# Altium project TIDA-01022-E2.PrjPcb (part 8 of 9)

## Sheet TIDA-01022-E2_Power3.SchDoc: Power Supplies
size 431 x 279 mm; Date: Not shown in title block; ApprovedBy: Not shown in title block; CheckedBy: Not shown in title block; Author: Not shown in title block; CompanyName: Not shown in title block; DrawnBy: Avinash N; Engineer: Not shown in title block; Organization: Not shown in title block; Address1: Not shown in title block; Address2: Not shown in title block; Address3: Not shown in title block; Address4: Not shown in title block; DocumentNumber: 1; Revision: Use project parameter SCH_Rev; SheetNumber: 23; SheetTotal: 26; PageSetup: Record=PageOptions¦CenterHorizontal=True¦CenterVertical=True¦PrintScale=1.00¦XCorrection=1.00¦YCorrection=1.00¦PrintKind=0¦BorderSize=5000000¦LeftOffset=0¦BottomOffset=0¦Orientation=2¦PaperLength=1000¦PaperWidth=1000¦Scale=100¦PaperSource=15¦PrintQuality=600¦MediaType=1¦DitherType=10¦PaperKind=Letter¦PrintScaleMode=1
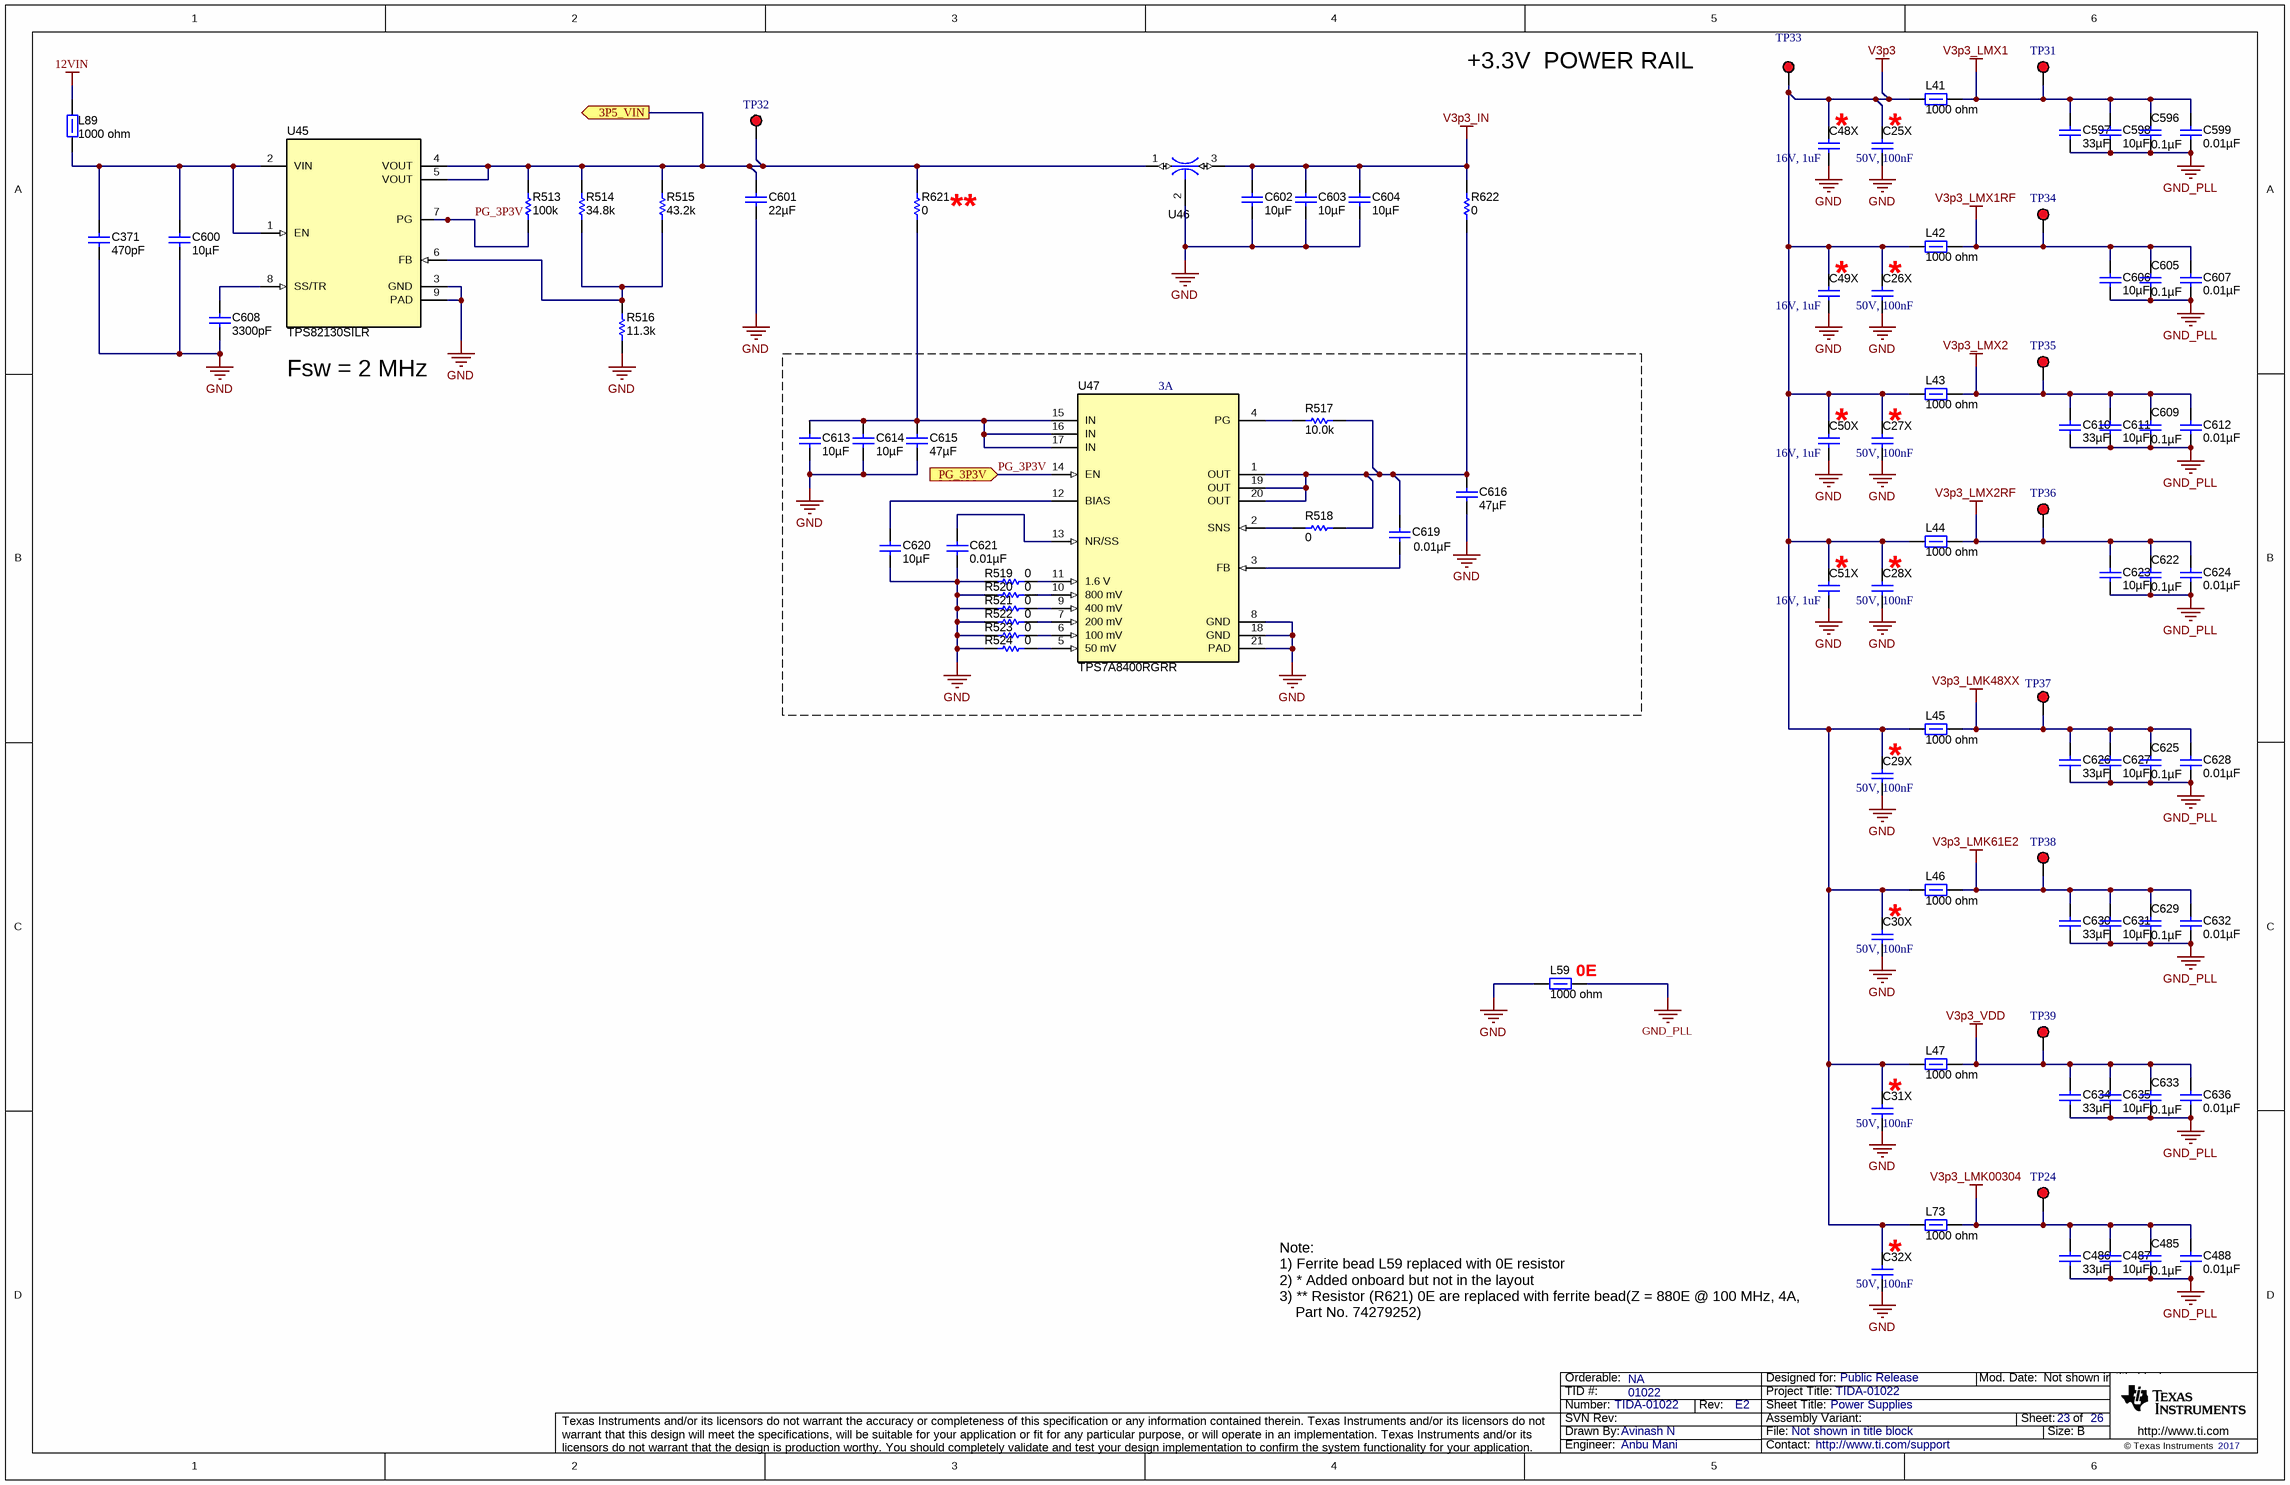
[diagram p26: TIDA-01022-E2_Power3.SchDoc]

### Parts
C25X  50V, 100nF  [0603_1.6x0.8x0.8mm_Reflow Soldering]
C26X  50V, 100nF  [0603_1.6x0.8x0.8mm_Reflow Soldering]
C27X  50V, 100nF  [0603_1.6x0.8x0.8mm_Reflow Soldering]
C28X  50V, 100nF  [0603_1.6x0.8x0.8mm_Reflow Soldering]
C29X  50V, 100nF  [0603_1.6x0.8x0.8mm_Reflow Soldering]
C30X  50V, 100nF  [0603_1.6x0.8x0.8mm_Reflow Soldering]
C31X  50V, 100nF  [0603_1.6x0.8x0.8mm_Reflow Soldering]
C32X  50V, 100nF  [0603_1.6x0.8x0.8mm_Reflow Soldering]
C48X  16V, 1uF  [0603_1.6x0.8x0.8mm_Reflow Soldering]
C49X  16V, 1uF  [0603_1.6x0.8x0.8mm_Reflow Soldering]
C50X  16V, 1uF  [0603_1.6x0.8x0.8mm_Reflow Soldering]
C51X  16V, 1uF  [0603_1.6x0.8x0.8mm_Reflow Soldering]
C371  ValueDisplayed: 470pF  [0402]  (hidden comment: GRM1555C1H471JA01D)
C485  ValueDisplayed: 0.1µF  [0603]  (hidden comment: CGA3E2X7R1H104K080AA)
C486  ValueDisplayed: 33µF  [1206_180]  (hidden comment: C3216X5R1E336M160AC)
C487  ValueDisplayed: 10µF  [1206_190]  (hidden comment: C3216X7R1E106M160AE)
C488  ValueDisplayed: 0.01µF  [0603]  (hidden comment: GCM188R71H103KA37D)
C596  ValueDisplayed: 0.1µF  [0603]  (hidden comment: CGA3E2X7R1H104K080AA)
C597  ValueDisplayed: 33µF  [1206_180]  (hidden comment: C3216X5R1E336M160AC)
C598  ValueDisplayed: 10µF  [1206_190]  (hidden comment: C3216X7R1E106M160AE)
C599  ValueDisplayed: 0.01µF  [0603]  (hidden comment: GCM188R71H103KA37D)
C600  ValueDisplayed: 10µF  [1206_190]  (hidden comment: C3216X7R1E106M160AE)
C601  ValueDisplayed: 22µF  [0805_HV]  (hidden comment: JMK212BJ226MG-T)
C602  ValueDisplayed: 10µF  [1206_190]  (hidden comment: C3216X7R1E106M160AE)
C603  ValueDisplayed: 10µF  [1206_190]  (hidden comment: C3216X7R1E106M160AE)
C604  ValueDisplayed: 10µF  [1206_190]  (hidden comment: C3216X7R1E106M160AE)
C605  ValueDisplayed: 0.1µF  [0603]  (hidden comment: CGA3E2X7R1H104K080AA)
C606  ValueDisplayed: 10µF  [1206_190]  (hidden comment: C3216X7R1E106M160AE)
C607  ValueDisplayed: 0.01µF  [0603]  (hidden comment: GCM188R71H103KA37D)
C608  ValueDisplayed: 3300pF  [0603]  (hidden comment: GRM1885C1H332JA01D)
C609  ValueDisplayed: 0.1µF  [0603]  (hidden comment: CGA3E2X7R1H104K080AA)
C610  ValueDisplayed: 33µF  [1206_180]  (hidden comment: C3216X5R1E336M160AC)
C611  ValueDisplayed: 10µF  [1206_190]  (hidden comment: C3216X7R1E106M160AE)
C612  ValueDisplayed: 0.01µF  [0603]  (hidden comment: GCM188R71H103KA37D)
C613  ValueDisplayed: 10µF  [0805_HV]  (hidden comment: GRM21BR61C106KE15L)
C614  ValueDisplayed: 10µF  [0805_HV]  (hidden comment: GRM21BR61C106KE15L)
C615  ValueDisplayed: 47µF  [0805_HV]  (hidden comment: GRM219R60G476ME44D)
C616  ValueDisplayed: 47µF  [0805_HV]  (hidden comment: GRM219R60G476ME44D)
C619  ValueDisplayed: 0.01µF  [0603]  (hidden comment: GRM188R71H103KA01D)
C620  ValueDisplayed: 10µF  [0805_HV]  (hidden comment: GRM21BR61C106KE15L)
C621  ValueDisplayed: 0.01µF  [0603]  (hidden comment: GRM188R71H103KA01D)
C622  ValueDisplayed: 0.1µF  [0603]  (hidden comment: CGA3E2X7R1H104K080AA)
C623  ValueDisplayed: 10µF  [1206_190]  (hidden comment: C3216X7R1E106M160AE)
C624  ValueDisplayed: 0.01µF  [0603]  (hidden comment: GCM188R71H103KA37D)
C625  ValueDisplayed: 0.1µF  [0603]  (hidden comment: CGA3E2X7R1H104K080AA)
C626  ValueDisplayed: 33µF  [1206_180]  (hidden comment: C3216X5R1E336M160AC)
C627  ValueDisplayed: 10µF  [1206_190]  (hidden comment: C3216X7R1E106M160AE)
C628  ValueDisplayed: 0.01µF  [0603]  (hidden comment: GCM188R71H103KA37D)
C629  ValueDisplayed: 0.1µF  [0603]  (hidden comment: CGA3E2X7R1H104K080AA)
C630  ValueDisplayed: 33µF  [1206_180]  (hidden comment: C3216X5R1E336M160AC)
C631  ValueDisplayed: 10µF  [1206_190]  (hidden comment: C3216X7R1E106M160AE)
C632  ValueDisplayed: 0.01µF  [0603]  (hidden comment: GCM188R71H103KA37D)
C633  ValueDisplayed: 0.1µF  [0603]  (hidden comment: CGA3E2X7R1H104K080AA)
C634  ValueDisplayed: 33µF  [1206_180]  (hidden comment: C3216X5R1E336M160AC)
C635  ValueDisplayed: 10µF  [1206_190]  (hidden comment: C3216X7R1E106M160AE)
C636  ValueDisplayed: 0.01µF  [0603]  (hidden comment: GCM188R71H103KA37D)
L41  ValueDisplayed: 1000 ohm  [1806_HighSpeed]  (hidden comment: BLM41PG102SN1L)
L42  ValueDisplayed: 1000 ohm  [1806_HighSpeed]  (hidden comment: BLM41PG102SN1L)
L43  ValueDisplayed: 1000 ohm  [1806_HighSpeed]  (hidden comment: BLM41PG102SN1L)
L44  ValueDisplayed: 1000 ohm  [1806_HighSpeed]  (hidden comment: BLM41PG102SN1L)
L45  ValueDisplayed: 1000 ohm  [1806_HighSpeed]  (hidden comment: BLM41PG102SN1L)
L46  ValueDisplayed: 1000 ohm  [1806_HighSpeed]  (hidden comment: BLM41PG102SN1L)
L47  ValueDisplayed: 1000 ohm  [1806_HighSpeed]  (hidden comment: BLM41PG102SN1L)
L59  ValueDisplayed: 1000 ohm  [1806_HighSpeed]  (hidden comment: BLM41PG102SN1L)
L73  ValueDisplayed: 1000 ohm  [1806_HighSpeed]  (hidden comment: BLM41PG102SN1L)
L89  ValueDisplayed: 1000 ohm  [1806_HighSpeed]  (hidden comment: BLM41PG102SN1L)
R513  ValueDisplayed: 100k  [0402]  (hidden comment: CRCW0402100KFKED)
R514  ValueDisplayed: 34.8k  [0603]  (hidden comment: CRCW060334K8FKEA)
R515  ValueDisplayed: 43.2k  [0402]  (hidden comment: CRCW040243K2FKED)
R516  ValueDisplayed: 11.3k  [0402]  (hidden comment: CRCW040211K3FKED)
R517  ValueDisplayed: 10.0k  [0603]  (hidden comment: CRCW060310K0FKEA)
R518  ValueDisplayed: 0  [0603]  (hidden comment: CRCW06030000Z0EA)
R519  ValueDisplayed: 0  [0402]  (hidden comment: CRCW04020000Z0ED)
R520  ValueDisplayed: 0  [0402]  (hidden comment: CRCW04020000Z0ED)
R521  ValueDisplayed: 0  [0402]  (hidden comment: CRCW04020000Z0ED)
R522  ValueDisplayed: 0  [0402]  (hidden comment: CRCW04020000Z0ED)
R523  ValueDisplayed: 0  [0402]  (hidden comment: CRCW04020000Z0ED)
R524  ValueDisplayed: 0  [0402]  (hidden comment: CRCW04020000Z0ED)
R621  ValueDisplayed: 0  [1206]  (hidden comment: CRCW12060000Z0EA)
R622  ValueDisplayed: 0  [1206]  (hidden comment: CRCW12060000Z0EA)
TP24  5000  [Keystone5000]  (value not drawn)
TP31  5000  [Keystone5000]  (value not drawn)
TP32  5000  [Keystone5000]  (value not drawn)
TP33  5000  [Keystone5000]  (value not drawn)
TP34  5000  [Keystone5000]  (value not drawn)
TP35  5000  [Keystone5000]  (value not drawn)
TP36  5000  [Keystone5000]  (value not drawn)
TP37  5000  [Keystone5000]  (value not drawn)
TP38  5000  [Keystone5000]  (value not drawn)
TP39  5000  [Keystone5000]  (value not drawn)
U45  TPS82130SILR  [SIL0008D_SMD]
U46  NFM31PC276B0J3L  [Murata_NFM31P]  (value not drawn)
U47  TPS7A8400RGRR  [RGR0020A]

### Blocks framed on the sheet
3A: C613-C616 C619-C621 R517-R524 U47

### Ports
3P5_VIN (out), PG_3P3V (in)

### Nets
12VIN: L89.2
GND: C25X.1 C26X.1 C27X.1 C28X.1 C29X.1 C30X.1 C31X.1 C32X.1 C48X.2 C49X.2 C50X.2 C51X.2 C371.2 C600.2 C601.2 C602.1 C603.1 C604.1 C608.1 C613.2 C614.2 C615.2 C616.2 C620.2 C621.2 L59.1 R516.1 R519.1 R520.1 R521.1 R522.1 R523.1 R524.1 U45.3(GND) U45.9(PAD) U46.2 U47.8(GND) U47.18(GND) U47.21(PAD)
GND_PLL: C485.2 C486.2 C487.1 C488.2 C596.2 C597.2 C598.1 C599.2 C605.2 C606.1 C607.2 C609.2 C610.2 C611.1 C612.2 C622.2 C623.1 C624.2 C625.2 C626.2 C627.1 C628.2 C629.2 C630.2 C631.1 C632.2 C633.2 C634.2 C635.1 C636.2 L59.2  [project net DGND]
V3p3: C25X.2 C26X.2 C27X.2 C28X.2 C29X.2 C30X.2 C31X.2 C32X.2 C48X.1 C49X.1 C50X.1 C51X.1 L41.1 L42.1 L43.1 L44.1 L45.1 L46.1 L47.1 L73.1 TP33.1
V3p3_IN: C602.2 C603.2 C604.2 R622.2 U46.3
V3p3_LMK48XX: C625.1 C626.1 C627.2 C628.1 L45.2 TP37.1
V3p3_LMK61E2: C629.1 C630.1 C631.2 C632.1 L46.2 TP38.1
V3p3_LMK00304: C485.1 C486.1 C487.2 C488.1 L73.2 TP24.1
V3p3_LMX1: C596.1 C597.1 C598.2 C599.1 L41.2 TP31.1
V3p3_LMX1RF: C605.1 C606.2 C607.1 L42.2 TP34.1
V3p3_LMX2: C609.1 C610.1 C611.2 C612.1 L43.2 TP35.1
V3p3_LMX2RF: C622.1 C623.2 C624.1 L44.2 TP36.1
V3p3_VDD: C633.1 C634.1 C635.2 C636.1 L47.2 TP39.1
3P5_VIN: C601.1 R513.2 R514.2 R515.2 R621.2 TP32.1 U45.4(VOUT) U45.5(VOUT) U46.1 ; port 3P5_VIN
PG_3P3V: R513.1 U45.7(PG) U47.14(EN) ; port PG_3P3V
NetC371_1: C371.1 C600.1 L89.1 U45.1(EN) U45.2(VIN)
NetC608_2: C608.2 U45.8(SS/TR)
NetC613_1: C613.1 C614.1 C615.1 R621.1 U47.15(IN) U47.16(IN) U47.17(IN)
NetC616_1: C616.1 C619.1 R517.1 R518.2 R622.1 U47.1(OUT) U47.19(OUT) U47.20(OUT)
NetC619_2: C619.2 U47.3(FB)
NetC620_1: C620.1 U47.12(BIAS)
NetC621_1: C621.1 U47.13(NR/SS)
NetR514_1: R514.1 R515.1 R516.2 U45.6(FB)
NetR517_2: R517.2 U47.4(PG)
NetR518_1: R518.1 U47.2(SNS)
NetR519_2: R519.2 U47.11(1.6_V)
NetR520_2: R520.2 U47.10(800_mV)
NetR521_2: R521.2 U47.9(400_mV)
NetR522_2: R522.2 U47.7(200_mV)
NetR523_2: R523.2 U47.6(100_mV)
NetR524_2: R524.2 U47.5(50_mV)

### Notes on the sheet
- +3.3V  POWER RAIL
- (near C48X) *
- (near C25X) *
- (near R621) *
- (near C49X) *
- (near C26X) *
- Fsw = 2 MHz
- (near C50X) *
- (near C27X) *
- (near C51X) *
- (near C28X) *
- (near C29X) *
- (near L59) 0E
- (near C30X) *
- (near C31X) *
- (near C32X) *
- Note:
  1) Ferrite bead L59 replaced with 0E resistor
  2) * Added onboard but not in the layout
  3) ** Resistor (R621) 0E are replaced with ferrite bead(Z = 880E @ 100 MHz, 4A,
  Part No. 74279252)

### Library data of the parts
C25X C26X C27X C28X C29X C30X C31X C32X = 885012206095: WCAP-CSGP Ceramic Capacitors, 0603, X7R, 50V, 100nF; Rated Voltage: 50V DC
C48X C49X C50X C51X = 885012206052: WCAP-CSGP Ceramic Capacitors, 0603, X7R, 16V, 1uF; Rated Voltage: 16V DC
C371 = GRM1555C1H471JA01D: CAP, CERM, 470 pF, 50 V, +/- 5%, C0G/NP0, 0402; Manufacturer: MuRata; Polarized: N; CompType: Capacitor; Value: 470pF; U/M: EA; Cap_F: 0.00000000047; Tolerance_%: 5; Value1: Unknown; VDC_V: 50; Value2: 50V; TaMin_C: -55; TaMax_C: 125; SizeArea_mm2: 0.5; SizeAreaWB_mm2: 3; SizeX_mm: 1; SizeZ_mm: 0.6; AEC Category: Q200
C485 C596 C605 C609 C622 C625 C629 C633 = CGA3E2X7R1H104K080AA: CAP, CERM, 0.1 µF, 50 V, +/- 10%, X7R, AEC-Q200 Grade 1, 0603; Manufacturer: TDK; Polarized: N; CompType: Capacitor; Value: 0.1uF; U/M: EA; Cap_F: 0.0000001; Tolerance_%: 10; ESR_ohm: 0.0296; Value1: 0.0296 ohm; VDC_V: 50; Value2: 50V; IRMS_A: 0.97199; TaMin_C: -55; TaMax_C: 125; SizeArea_mm2: 1.28; SizeAreaWB_mm2: 4.68; SizeX_mm: 1.6; SizeY_mm: 0.8; SizeZ_mm: 1; AEC Category: Q200; AEC Qualified: Y
C486 C597 C610 C626 C630 C634 = C3216X5R1E336M160AC: CAP, CERM, 33 µF, 25 V, +/- 20%, X5R, 1206; Manufacturer: TDK; Polarized: N; CompType: Capacitor; Value: 33uF; U/M: EA; Cap_F: 0.000033; Tolerance_%: 20; ESR_ohm: 0.002648; Value1: 0.002648 ohm; VDC_V: 25; Value2: 25V; IRMS_A: 4.45864; TaMin_C: -55; TaMax_C: 85; SizeArea_mm2: 5.12; SizeAreaWB_mm2: 10.92; SizeX_mm: 3.2; SizeY_mm: 1.6; SizeZ_mm: 1.8; AEC Category: Q200
C487 C598 C600 C602-C604 C606 C611 C623 C627 C631 C635 = C3216X7R1E106M160AE: CAP, CERM, 10 µF, 25 V, +/- 20%, X7R, 1206_190; Manufacturer: TDK; Polarized: N; CompType: Capacitor; Value: 10uF; U/M: EA; Cap_F: 0.00001; Tolerance_%: 20; Value1: Unknown; VDC_V: 25; Value2: 25V; TaMin_C: -55; TaMax_C: 125; Cap_Case: 1206; SizeArea_mm2: 5.12; SizeAreaWB_mm2: 10.92; SizeX_mm: 3.2; SizeY_mm: 1.6; SizeZ_mm: 1.9; AEC Category: Q200
C488 C599 C607 C612 C624 C628 C632 C636 = GCM188R71H103KA37D: CAP, CERM, 0.01 µF, 50 V, +/- 10%, X7R, AEC-Q200 Grade 1, 0603; Manufacturer: MuRata; Polarized: N; CompType: Capacitor; Value: 0.01uF; U/M: EA; Cap_F: 0.00000001; Tolerance_%: 10; Value1: Unknown; VDC_V: 50; Value2: 50V; TaMin_C: -55; TaMax_C: 125; SizeArea_mm2: 1.28; SizeAreaWB_mm2: 4.68; SizeX_mm: 1.6; SizeY_mm: 0.8; SizeZ_mm: 1; AEC Category: Q200; AEC Qualified: Y
C601 = JMK212BJ226MG-T: CAP, CERM, 22 µF, 6.3 V, +/- 20%, X5R, 0805; Manufacturer: Taiyo Yuden; Polarized: N; CompType: Capacitor; Value: 22uF; U/M: EA; Cap_F: 0.000022; Tolerance_%: 20; Value1: Unknown; VDC_V: 6.3; Value2: 6.3V; TaMin_C: -55; TaMax_C: 85; Cap_Case: 0805; SizeArea_mm2: 2.5; SizeAreaWB_mm2: 6.75; SizeX_mm: 2; SizeY_mm: 1.25; SizeZ_mm: 1.45; AEC Category: Q200
C608 = GRM1885C1H332JA01D: CAP, CERM, 3300 pF, 50 V, +/- 5%, C0G/NP0, 0603; Manufacturer: MuRata; Polarized: N; CompType: Capacitor; Value: 3300pF; U/M: EA; Cap_F: 0.0000000033; Tolerance_%: 5; Value1: Unknown; VDC_V: 50; Value2: 50V; TaMin_C: -55; TaMax_C: 125; SizeArea_mm2: 1.28; SizeAreaWB_mm2: 4.68; SizeX_mm: 1.6; SizeY_mm: 0.8; SizeZ_mm: 1; AEC Category: Q200
C613 C614 C620 = GRM21BR61C106KE15L: CAP, CERM, 10 µF, 16 V, +/- 10%, X5R, 0805; Manufacturer: MuRata; Polarized: N; CompType: Capacitor; Value: 10uF; U/M: EA; Cap_F: 0.00001; Tolerance_%: 10; ESR_ohm: 0.008; Value1: 0.008 ohm; VDC_V: 16; Value2: 16V; TaMin_C: -55; TaMax_C: 85; Cap_Case: 0805; SizeArea_mm2: 2.5; SizeAreaWB_mm2: 6.75; SizeX_mm: 2; SizeY_mm: 1.25; SizeZ_mm: 1.45; AEC Category: Q200
C615 C616 = GRM219R60G476ME44D: CAP, CERM, 47 µF, 4 V, +/- 20%, X5R, 0805; Manufacturer: MuRata; Polarized: N; CompType: Capacitor; Value: 47uF; U/M: EA; Cap_F: 0.000047; Tolerance_%: 20; Value1: Unknown; VDC_V: 4; Value2: 4V; TaMin_C: -55; TaMax_C: 85; Cap_Case: 0805; SizeArea_mm2: 2.5; SizeAreaWB_mm2: 6.75; SizeX_mm: 2; SizeY_mm: 1.25; SizeZ_mm: 1.45; AEC Category: Q200
C619 C621 = GRM188R71H103KA01D: CAP, CERM, 0.01 µF, 50 V, +/- 10%, X7R, 0603; Manufacturer: MuRata; Polarized: N; CompType: Capacitor; Value: 0.01uF; U/M: EA; Cap_F: 0.00000001; Tolerance_%: 10; Value1: Unknown; VDC_V: 50; Value2: 50V; TaMin_C: -55; TaMax_C: 125; SizeArea_mm2: 1.28; SizeAreaWB_mm2: 4.68; SizeX_mm: 1.6; SizeY_mm: 0.8; SizeZ_mm: 1; AEC Category: Q200
L41-L47 L59 L73 L89 = BLM41PG102SN1L: Ferrite Bead, 1000 ohm @ 100 MHz, 1.5 A, 1806; Manufacturer: MuRata; Imax_A: 1.5; DCR_ohm: 0.09; Value1: 0.09 ohm; Value2: 1.5A; SizeAreaWB_mm2: 14.3; SizeArea_mm2: 7.2; SizeX_mm: 4.5; SizeY_mm: 1.6; SizeZ_mm: 1.85; ZTyp@100MHz_Ohm: 1000
R513 = CRCW0402100KFKED: RES, 100 k, 1%, 0.063 W, 0402; Manufacturer: Vishay-Dale; CompType: Resistor; Value: 100k; Res_ohm: 100000; Tolerance_%: 1; Power_W: 0.063; Value2: 0.063W; VDC_V: 50; TempCo: 100 ppm/C; SizeArea_mm2: 0.5; SizeZ_mm: 0.6; EIA_Code: E96; U/M: EA; AEC Category: Q200
R514 = CRCW060334K8FKEA: RES, 34.8 k, 1%, 0.1 W, 0603; Manufacturer: Vishay-Dale; CompType: Resistor; Value: 34.8k; Res_ohm: 34800; Value_Code: 34k8; Tolerance_%: 1; Power_W: 0.1; Value2: 0.1W; VDC_V: 75; TempCo: 100 ppm/C; SizeArea_mm2: 1.28; SizeX_mm: 1.6; SizeY_mm: 0.8; EIA_Code: E96; U/M: EA; AEC Category: Q200
R515 = CRCW040243K2FKED: RES, 43.2 k, 1%, 0.063 W, 0402; Manufacturer: Vishay-Dale; CompType: Resistor; Value: 43.2k; Res_ohm: 43200; Value_Code: 43k2; Tolerance_%: 1; Power_W: 0.063; Value2: 0.063W; VDC_V: 50; TempCo: 100 ppm/C; SizeArea_mm2: 0.5; SizeZ_mm: 0.6; EIA_Code: E96; U/M: EA; AEC Category: Q200
R516 = CRCW040211K3FKED: RES, 11.3 k, 1%, 0.063 W, 0402; Manufacturer: Vishay-Dale; CompType: Resistor; Value: 11.3k; Res_ohm: 11300; Value_Code: 11k3; Tolerance_%: 1; Power_W: 0.063; Value2: 0.063W; VDC_V: 50; TempCo: 100 ppm/C; SizeArea_mm2: 0.5; SizeZ_mm: 0.6; EIA_Code: E96; U/M: EA; AEC Category: Q200
R517 = CRCW060310K0FKEA: RES, 10.0 k, 1%, 0.1 W, 0603; Manufacturer: Vishay-Dale; CompType: Resistor; Value: 10.0k; Res_ohm: 10000; Value_Code: 10k0; Tolerance_%: 1; Power_W: 0.1; Value2: 0.1W; VDC_V: 75; TempCo: 100 ppm/C; SizeArea_mm2: 1.28; SizeX_mm: 1.6; SizeY_mm: 0.8; EIA_Code: E96; U/M: EA; AEC Category: Q200
R518 = CRCW06030000Z0EA: RES, 0, 5%, 0.1 W, 0603; Manufacturer: Vishay-Dale; CompType: Resistor; Value: 0; Value_Code: 0000; Tolerance_%: 5; Power_W: 0.1; Value2: 0.1W; VDC_V: 75; TempCo: 200 ppm/C; SizeArea_mm2: 1.28; SizeX_mm: 1.6; SizeY_mm: 0.8; SizeZ_mm: 1; EIA_Code: E24; U/M: EA; AEC Category: Q200
R519-R524 = CRCW04020000Z0ED: RES, 0, 5%, 0.063 W, 0402; Manufacturer: Vishay-Dale; CompType: Resistor; Value: 0; Value_Code: 0000; Tolerance_%: 5; Power_W: 0.063; Value2: 0.063W; VDC_V: 50; TempCo: 200 ppm/C; SizeArea_mm2: 0.5; SizeX_mm: 1; SizeZ_mm: 0.6; EIA_Code: E24; U/M: EA; AEC Category: Q200
R621 R622 = CRCW12060000Z0EA: RES, 0, 5%, 0.25 W, 1206; Manufacturer: Vishay-Dale; CompType: Resistor; Value: 0; Value_Code: 0000; Tolerance_%: 5; Power_W: 0.25; Value2: 0.25W; VDC_V: 200; TempCo: 200 ppm/C; SizeArea_mm2: 5.12; SizeX_mm: 3.2; SizeY_mm: 1.6; SizeZ_mm: 1.35; EIA_Code: E24; U/M: EA; AEC Category: Q200
TP24 TP31-TP39 = 5000: Test Point, Miniature, Red, TH; Manufacturer: Keystone; CompType: Test Point Loop; ContactFinish: Silver; Green_Lifecycle: Active; Green_REACh: Passed
U45 = TPS82130SILR: 3-A 17V Step-down Converter Module with Integrated Inductor, SIL0008D (uSIP-8); Alternate PartNumber: TPS82130SILT; Manufacturer: Texas Instruments; SymbolCreator: Altium; SizeArea_mm2: 12.25; SizeAreaWB_mm2: 20.25; SizeX_mm: 3.5; SizeZ_mm: 1.53; CompType: IC; U/M: EA
U46 = NFM31PC276B0J3L: FILTER LC HIGH FREQ 27uF 1206; Manufacturer: MuRata; SymbolCreator: Altium
U47 = TPS7A8400RGRR: High-Current (3 A), High-Accuracy (1%), Low-Noise (4.4 μVRMS), LDO Voltage Regulator, RGR0020A (VQFN-20); Alternate PartNumber: TPS7A8400RGRT; Manufacturer: Texas Instruments; SymbolCreator: a0411947; SizeArea_mm2: 12.25; SizeAreaWB_mm2: 20.25; SizeX_mm: 3.5; SizeZ_mm: 1; CompType: IC; U/M: EA

## Sheet TIDA-01022-E2_Power4.SchDoc: Power Supplies
size 431 x 279 mm; Date: Not shown in title block; ApprovedBy: Not shown in title block; CheckedBy: Not shown in title block; Author: Not shown in title block; CompanyName: Not shown in title block; DrawnBy: Avinash N; Engineer: Not shown in title block; Organization: Not shown in title block; Address1: Not shown in title block; Address2: Not shown in title block; Address3: Not shown in title block; Address4: Not shown in title block; DocumentNumber: 1; Revision: Use project parameter SCH_Rev; SheetNumber: 24; SheetTotal: 26; PageSetup: Record=PageOptions¦CenterHorizontal=True¦CenterVertical=True¦PrintScale=1.00¦XCorrection=1.00¦YCorrection=1.00¦PrintKind=0¦BorderSize=5000000¦LeftOffset=0¦BottomOffset=0¦Orientation=2¦PaperLength=1000¦PaperWidth=1000¦Scale=100¦PaperSource=15¦PrintQuality=600¦MediaType=1¦DitherType=10¦PaperKind=Letter¦PrintScaleMode=1
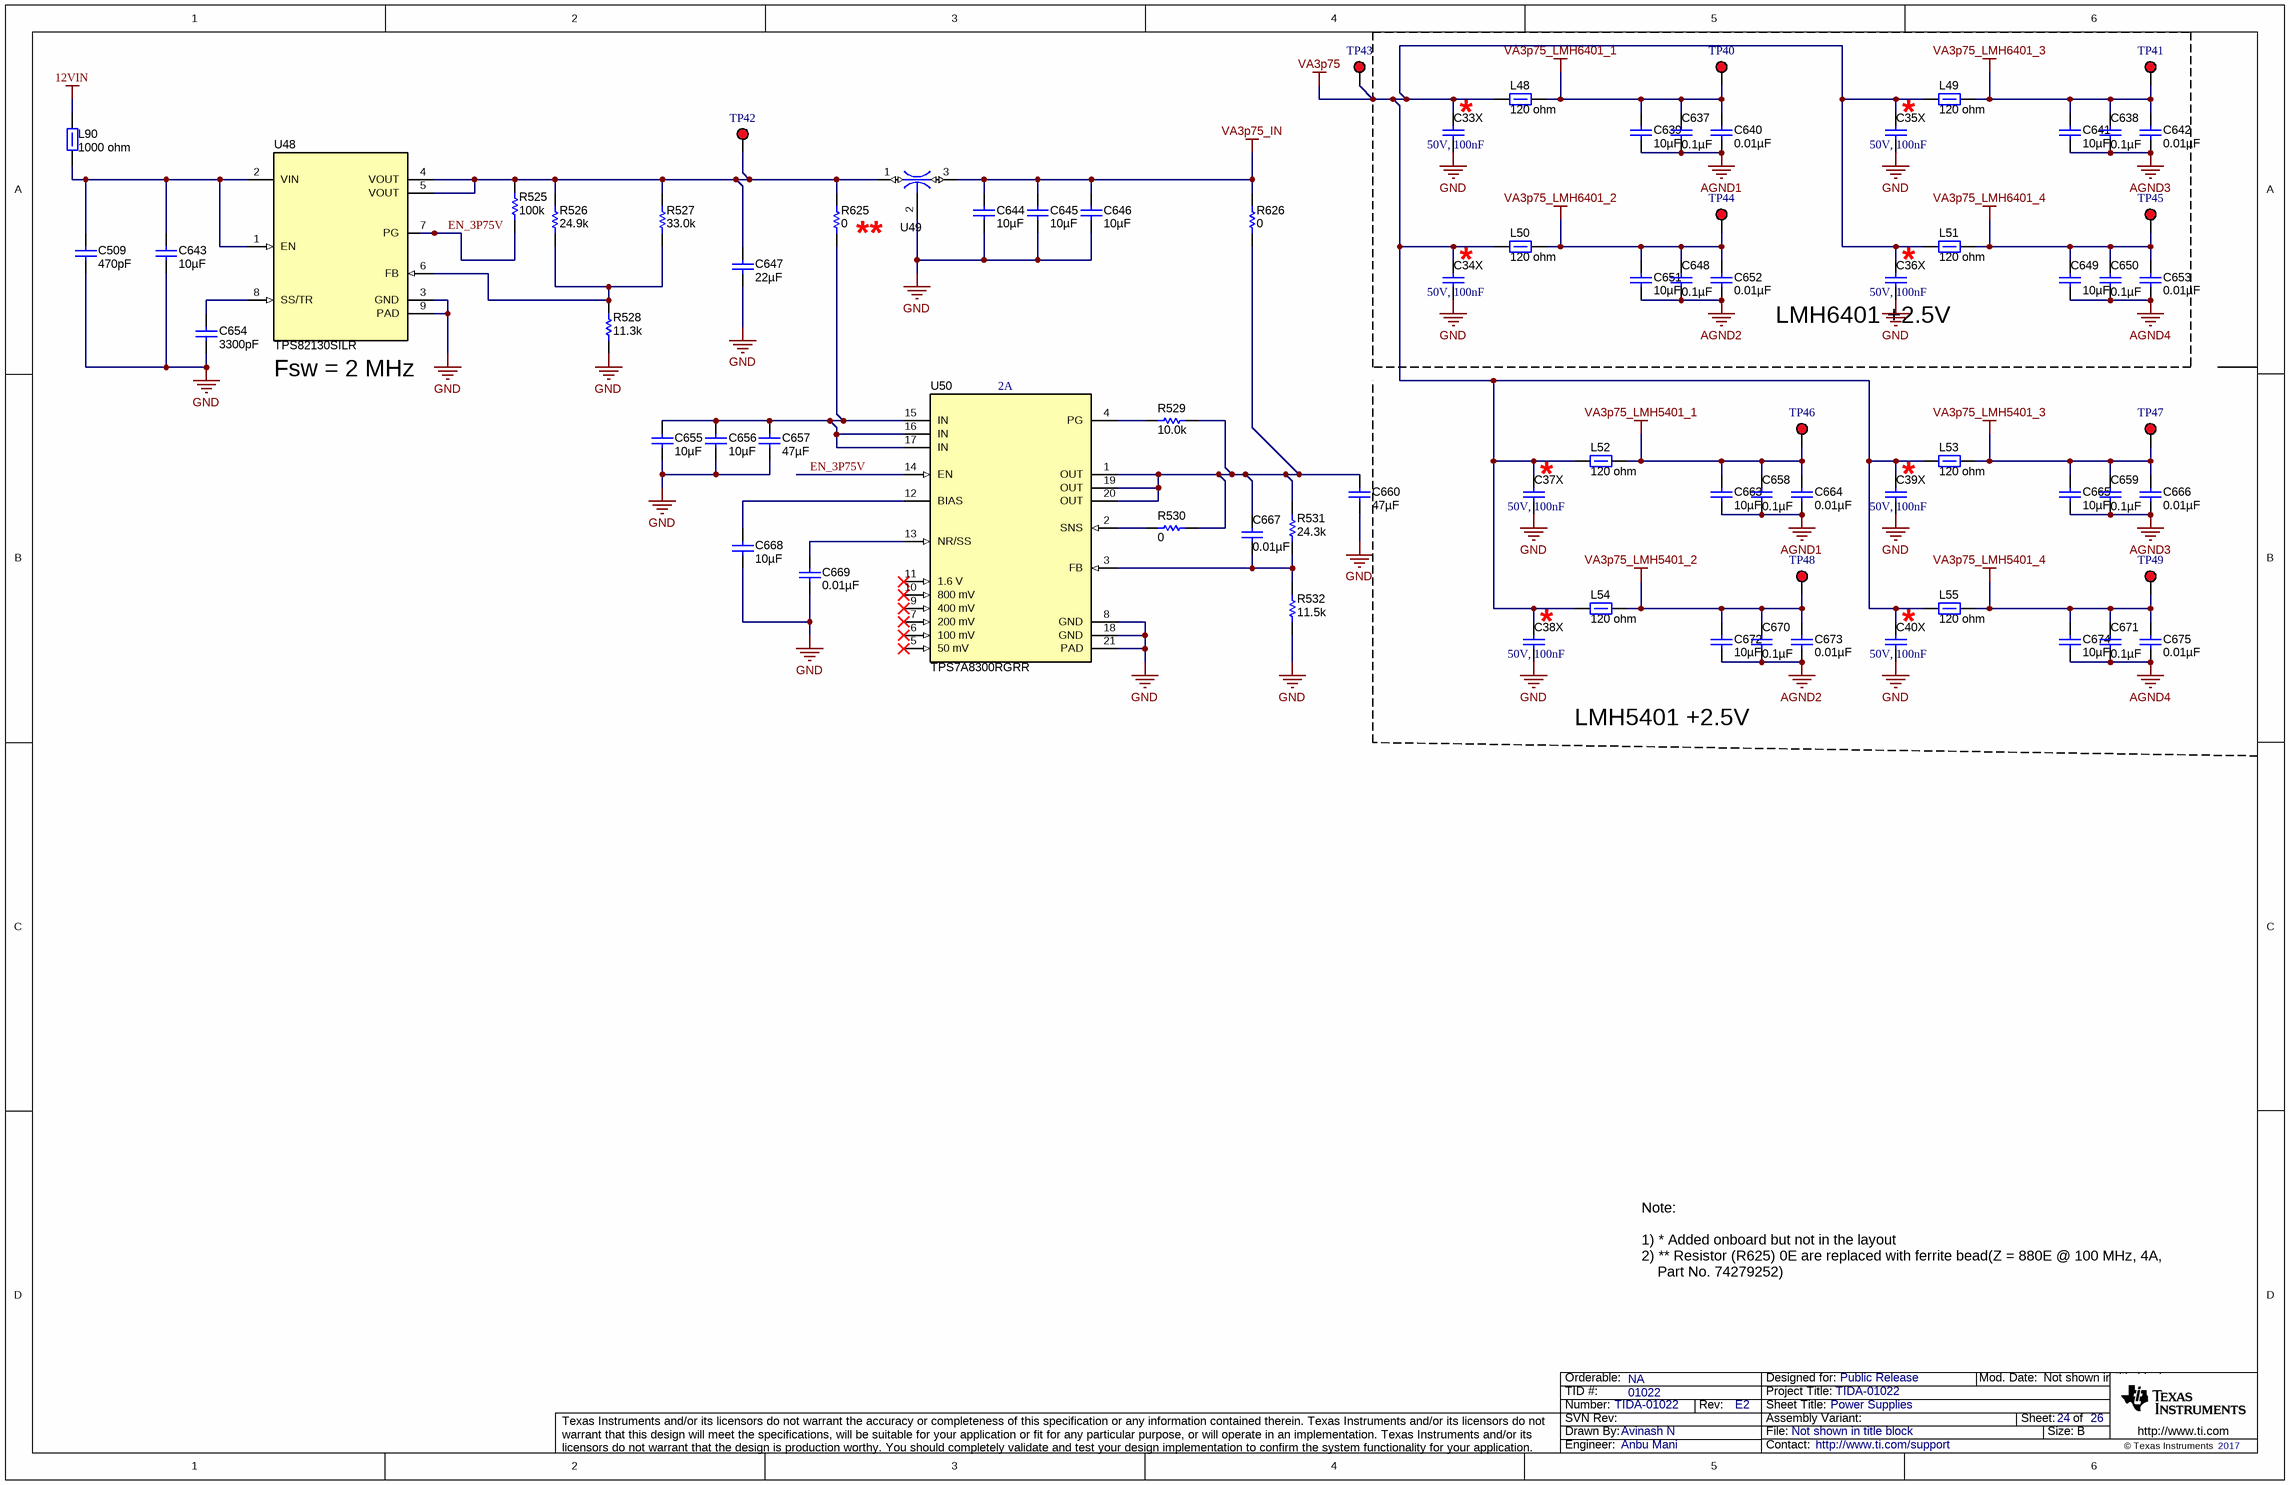
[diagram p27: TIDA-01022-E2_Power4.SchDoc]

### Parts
C33X  50V, 100nF  [0603_1.6x0.8x0.8mm_Reflow Soldering]
C34X  50V, 100nF  [0603_1.6x0.8x0.8mm_Reflow Soldering]
C35X  50V, 100nF  [0603_1.6x0.8x0.8mm_Reflow Soldering]
C36X  50V, 100nF  [0603_1.6x0.8x0.8mm_Reflow Soldering]
C37X  50V, 100nF  [0603_1.6x0.8x0.8mm_Reflow Soldering]
C38X  50V, 100nF  [0603_1.6x0.8x0.8mm_Reflow Soldering]
C39X  50V, 100nF  [0603_1.6x0.8x0.8mm_Reflow Soldering]
C40X  50V, 100nF  [0603_1.6x0.8x0.8mm_Reflow Soldering]
C509  ValueDisplayed: 470pF  [0402]  (hidden comment: GRM1555C1H471JA01D)
C637  ValueDisplayed: 0.1µF  [0603]  (hidden comment: CGA3E2X7R1H104K080AA)
C638  ValueDisplayed: 0.1µF  [0603]  (hidden comment: CGA3E2X7R1H104K080AA)
C639  ValueDisplayed: 10µF  [1206_190]  (hidden comment: C3216X7R1E106M160AE)
C640  ValueDisplayed: 0.01µF  [0603]  (hidden comment: GCM188R71H103KA37D)
C641  ValueDisplayed: 10µF  [1206_190]  (hidden comment: C3216X7R1E106M160AE)
C642  ValueDisplayed: 0.01µF  [0603]  (hidden comment: GCM188R71H103KA37D)
C643  ValueDisplayed: 10µF  [1206_190]  (hidden comment: C3216X7R1E106M160AE)
C644  ValueDisplayed: 10µF  [1206_190]  (hidden comment: C3216X7R1E106M160AE)
C645  ValueDisplayed: 10µF  [1206_190]  (hidden comment: C3216X7R1E106M160AE)
C646  ValueDisplayed: 10µF  [1206_190]  (hidden comment: C3216X7R1E106M160AE)
C647  ValueDisplayed: 22µF  [0805_HV]  (hidden comment: JMK212BJ226MG-T)
C648  ValueDisplayed: 0.1µF  [0603]  (hidden comment: CGA3E2X7R1H104K080AA)
C649  ValueDisplayed: 10µF  [1206_190]  (hidden comment: C3216X7R1E106M160AE)
C650  ValueDisplayed: 0.1µF  [0603]  (hidden comment: CGA3E2X7R1H104K080AA)
C651  ValueDisplayed: 10µF  [1206_190]  (hidden comment: C3216X7R1E106M160AE)
C652  ValueDisplayed: 0.01µF  [0603]  (hidden comment: GCM188R71H103KA37D)
C653  ValueDisplayed: 0.01µF  [0603]  (hidden comment: GCM188R71H103KA37D)
C654  ValueDisplayed: 3300pF  [0603]  (hidden comment: GRM1885C1H332JA01D)
C655  ValueDisplayed: 10µF  [0805_HV]  (hidden comment: GRM21BR61C106KE15L)
C656  ValueDisplayed: 10µF  [0805_HV]  (hidden comment: GRM21BR61C106KE15L)
C657  ValueDisplayed: 47µF  [0805_HV]  (hidden comment: GRM219R60G476ME44D)
C658  ValueDisplayed: 0.1µF  [0603]  (hidden comment: CGA3E2X7R1H104K080AA)
C659  ValueDisplayed: 0.1µF  [0603]  (hidden comment: CGA3E2X7R1H104K080AA)
C660  ValueDisplayed: 47µF  [0805_HV]  (hidden comment: GRM219R60G476ME44D)
C663  ValueDisplayed: 10µF  [1206_190]  (hidden comment: C3216X7R1E106M160AE)
C664  ValueDisplayed: 0.01µF  [0603]  (hidden comment: GCM188R71H103KA37D)
C665  ValueDisplayed: 10µF  [1206_190]  (hidden comment: C3216X7R1E106M160AE)
C666  ValueDisplayed: 0.01µF  [0603]  (hidden comment: GCM188R71H103KA37D)
C667  ValueDisplayed: 0.01µF  [0603]  (hidden comment: GRM188R71H103KA01D)
C668  ValueDisplayed: 10µF  [0805_HV]  (hidden comment: GRM21BR61C106KE15L)
C669  ValueDisplayed: 0.01µF  [0603]  (hidden comment: GRM188R71H103KA01D)
C670  ValueDisplayed: 0.1µF  [0603]  (hidden comment: CGA3E2X7R1H104K080AA)
C671  ValueDisplayed: 0.1µF  [0603]  (hidden comment: CGA3E2X7R1H104K080AA)
C672  ValueDisplayed: 10µF  [1206_190]  (hidden comment: C3216X7R1E106M160AE)
C673  ValueDisplayed: 0.01µF  [0603]  (hidden comment: GCM188R71H103KA37D)
C674  ValueDisplayed: 10µF  [1206_190]  (hidden comment: C3216X7R1E106M160AE)
C675  ValueDisplayed: 0.01µF  [0603]  (hidden comment: GCM188R71H103KA37D)
L48  ValueDisplayed: 120 ohm  [0603]  (hidden comment: BLM18SG121TN1D)
L49  ValueDisplayed: 120 ohm  [0603]  (hidden comment: BLM18SG121TN1D)
L50  ValueDisplayed: 120 ohm  [0603]  (hidden comment: BLM18SG121TN1D)
L51  ValueDisplayed: 120 ohm  [0603]  (hidden comment: BLM18SG121TN1D)
L52  ValueDisplayed: 120 ohm  [0603]  (hidden comment: BLM18SG121TN1D)
L53  ValueDisplayed: 120 ohm  [0603]  (hidden comment: BLM18SG121TN1D)
L54  ValueDisplayed: 120 ohm  [0603]  (hidden comment: BLM18SG121TN1D)
L55  ValueDisplayed: 120 ohm  [0603]  (hidden comment: BLM18SG121TN1D)
L90  ValueDisplayed: 1000 ohm  [1806_HighSpeed]  (hidden comment: BLM41PG102SN1L)
R525  ValueDisplayed: 100k  [0402]  (hidden comment: CRCW0402100KFKED)
R526  ValueDisplayed: 24.9k  [0603]  (hidden comment: CRCW060324K9FKEA)
R527  ValueDisplayed: 33.0k  [0402]  (hidden comment: ERA-2AEB333X)
R528  ValueDisplayed: 11.3k  [0402]  (hidden comment: CRCW040211K3FKED)
R529  ValueDisplayed: 10.0k  [0603]  (hidden comment: CRCW060310K0FKEA)
R530  ValueDisplayed: 0  [0603]  (hidden comment: CRCW06030000Z0EA)
R531  ValueDisplayed: 24.3k  [0603]  (hidden comment: CRCW060324K3FKEA)
R532  ValueDisplayed: 11.5k  [0603]  (hidden comment: CRCW060311K5FKEA)
R625  ValueDisplayed: 0  [1206]  (hidden comment: CRCW12060000Z0EA)
R626  ValueDisplayed: 0  [1206]  (hidden comment: CRCW12060000Z0EA)
TP40  5000  [Keystone5000]  (value not drawn)
TP41  5000  [Keystone5000]  (value not drawn)
TP42  5000  [Keystone5000]  (value not drawn)
TP43  5000  [Keystone5000]  (value not drawn)
TP44  5000  [Keystone5000]  (value not drawn)
TP45  5000  [Keystone5000]  (value not drawn)
TP46  5000  [Keystone5000]  (value not drawn)
TP47  5000  [Keystone5000]  (value not drawn)
TP48  5000  [Keystone5000]  (value not drawn)
TP49  5000  [Keystone5000]  (value not drawn)
U48  TPS82130SILR  [SIL0008D_SMD]
U49  NFM31PC276B0J3L  [Murata_NFM31P]  (value not drawn)
U50  TPS7A8300RGRR  [RGR0020A]

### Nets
12VIN: L90.2
AGND1: C637.2 C638.2 C639.1 C640.2 C641.1 C642.2 C648.2 C649.1 C650.2 C651.1 C652.2 C653.2 C658.2 C659.2 C663.1 C664.2 C665.1 C666.2 C670.2 C671.2 C672.1 C673.2 C674.1 C675.2  [also labelled AGND2, AGND3, AGND4]  [project net AGND]
GND: C33X.1 C34X.1 C35X.1 C36X.1 C37X.1 C38X.1 C39X.1 C40X.1 C509.2 C643.2 C644.1 C645.1 C646.1 C647.2 C654.1 C655.2 C656.2 C657.2 C660.2 C668.2 C669.2 R528.1 R532.1 U48.3(GND) U48.9(PAD) U49.2 U50.8(GND) U50.18(GND) U50.21(PAD)
VA3p75: C33X.2 C34X.2 C35X.2 C36X.2 C37X.2 C38X.2 C39X.2 C40X.2 L48.1 L49.1 L50.1 L51.1 L52.1 L53.1 L54.1 L55.1 TP43.1
VA3p75_IN: C644.2 C645.2 C646.2 R626.2 U49.3
VA3p75_LMH5401_1: C658.1 C663.2 C664.1 L52.2 TP46.1
VA3p75_LMH5401_2: C670.1 C672.2 C673.1 L54.2 TP48.1
VA3p75_LMH5401_3: C659.1 C665.2 C666.1 L53.2 TP47.1
VA3p75_LMH5401_4: C671.1 C674.2 C675.1 L55.2 TP49.1
VA3p75_LMH6401_1: C637.1 C639.2 C640.1 L48.2 TP40.1
VA3p75_LMH6401_2: C648.1 C651.2 C652.1 L50.2 TP44.1
VA3p75_LMH6401_3: C638.1 C641.2 C642.1 L49.2 TP41.1
VA3p75_LMH6401_4: C649.2 C650.1 C653.1 L51.2 TP45.1
EN_3P75V: R525.1 U48.7(PG) U50.14(EN)
NetC509_1: C509.1 C643.1 L90.1 U48.1(EN) U48.2(VIN)
NetC647_1: C647.1 R525.2 R526.2 R527.2 R625.2 TP42.1 U48.4(VOUT) U48.5(VOUT) U49.1
NetC654_2: C654.2 U48.8(SS/TR)
NetC655_1: C655.1 C656.1 C657.1 R625.1 U50.15(IN) U50.16(IN) U50.17(IN)
NetC660_1: C660.1 C667.1 R529.1 R530.2 R531.2 R626.1 U50.1(OUT) U50.19(OUT) U50.20(OUT)
NetC667_2: C667.2 R531.1 R532.2 U50.3(FB)
NetC668_1: C668.1 U50.12(BIAS)
NetC669_1: C669.1 U50.13(NR/SS)
NetR526_1: R526.1 R527.1 R528.2 U48.6(FB)
NetR529_2: R529.2 U50.4(PG)
NetR530_1: R530.1 U50.2(SNS)

Not connected (* = marked no-connect by the designer): U50 5(50_mV)* 6(100_mV)* 7(200_mV)* 9(400_mV)* 10(800_mV)* 11(1.6_V)*

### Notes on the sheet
- (near C33X) *
- (near C35X) *
- (near R625) *
- *
- (near C34X) *
- (near C36X) *
- (near C36X) LMH6401 +2.5V
- (near U48) Fsw = 2 MHz
- (near U50) 2A
- (near C37X) *
- (near C39X) *
- (near C38X) *
- (near C40X) *
- LMH5401 +2.5V
- Note:
  1) * Added onboard but not in the layout
  2) ** Resistor (R625) 0E are replaced with ferrite bead(Z = 880E @ 100 MHz, 4A,
  Part No. 74279252)

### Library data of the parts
C33X C34X C35X C36X C37X C38X C39X C40X = 885012206095: as C25X on sheet TIDA-01022-E2_Power3
C509 = GRM1555C1H471JA01D: as C371 on sheet TIDA-01022-E2_Power3
C637 C638 C648 C650 C658 C659 C670 C671 = CGA3E2X7R1H104K080AA: as C485 on sheet TIDA-01022-E2_Power3
C639 C641 C643-C646 C649 C651 C663 C665 C672 C674 = C3216X7R1E106M160AE: as C487 on sheet TIDA-01022-E2_Power3
C640 C642 C652 C653 C664 C666 C673 C675 = GCM188R71H103KA37D: as C488 on sheet TIDA-01022-E2_Power3
C647 = JMK212BJ226MG-T: as C601 on sheet TIDA-01022-E2_Power3
C654 = GRM1885C1H332JA01D: as C608 on sheet TIDA-01022-E2_Power3
C655 C656 C668 = GRM21BR61C106KE15L: as C613 on sheet TIDA-01022-E2_Power3
C657 C660 = GRM219R60G476ME44D: as C615 on sheet TIDA-01022-E2_Power3
C667 C669 = GRM188R71H103KA01D: as C619 on sheet TIDA-01022-E2_Power3
L48-L55 = BLM18SG121TN1D: Ferrite Bead, 120 ohm @ 100 MHz, 3 A, 0603; Manufacturer: MuRata; Value: 120 ohm; Imax_A: 3; DCR_ohm: 0.025; Value1: 0.025 ohm; Value2: 3A; SizeAreaWB_mm2: 4.68; SizeArea_mm2: 1.28; SizeX_mm: 1.6; SizeY_mm: 0.8; SizeZ_mm: 1; ZTyp@100MHz_Ohm: 120
L90 = BLM41PG102SN1L: as L41-L47 on sheet TIDA-01022-E2_Power3
R525 = CRCW0402100KFKED: as R513 on sheet TIDA-01022-E2_Power3
R526 = CRCW060324K9FKEA: RES, 24.9 k, 1%, 0.1 W, 0603; Manufacturer: Vishay-Dale; CompType: Resistor; Value: 24.9k; Res_ohm: 24900; Value_Code: 24k9; Tolerance_%: 1; Power_W: 0.1; Value2: 0.1W; VDC_V: 75; TempCo: 100 ppm/C; SizeArea_mm2: 1.28; SizeX_mm: 1.6; SizeY_mm: 0.8; EIA_Code: E96; U/M: EA; AEC Category: Q200
R527 = ERA-2AEB333X: RES, 33.0 k, 0.1%, 0.063 W, 0402; Manufacturer: Panasonic; CompType: Resistor; Value: 33.0k; Res_ohm: 33000; Value_Code: 33k0; Tolerance_%: 0.1; Power_W: 0.063; Value2: 0.063W; VDC_V: 50; TempCo: 25 ppm/C; SizeArea_mm2: 0.5; SizeX_mm: 1; SizeZ_mm: 0.6; U/M: EA; AEC Category: Q200
R528 = CRCW040211K3FKED: as R516 on sheet TIDA-01022-E2_Power3
R529 = CRCW060310K0FKEA: as R517 on sheet TIDA-01022-E2_Power3
R530 = CRCW06030000Z0EA: as R518 on sheet TIDA-01022-E2_Power3
R531 = CRCW060324K3FKEA: RES, 24.3 k, 1%, 0.1 W, 0603; Manufacturer: Vishay-Dale; CompType: Resistor; Value: 24.3k; Res_ohm: 24300; Value_Code: 24k3; Tolerance_%: 1; Power_W: 0.1; Value2: 0.1W; VDC_V: 75; TempCo: 100 ppm/C; SizeArea_mm2: 1.28; SizeX_mm: 1.6; SizeY_mm: 0.8; EIA_Code: E96; U/M: EA; AEC Category: Q200
R532 = CRCW060311K5FKEA: RES, 11.5 k, 1%, 0.1 W, 0603; Manufacturer: Vishay-Dale; CompType: Resistor; Value: 11.5k; Res_ohm: 11500; Value_Code: 11k5; Tolerance_%: 1; Power_W: 0.1; Value2: 0.1W; VDC_V: 75; TempCo: 100 ppm/C; SizeArea_mm2: 1.28; SizeX_mm: 1.6; SizeY_mm: 0.8; EIA_Code: E96; U/M: EA; AEC Category: Q200
R625 R626 = CRCW12060000Z0EA: as R621 on sheet TIDA-01022-E2_Power3
TP40-TP49 = 5000: as TP24 on sheet TIDA-01022-E2_Power3
U48 = TPS82130SILR: as U45 on sheet TIDA-01022-E2_Power3
U49 = NFM31PC276B0J3L: as U46 on sheet TIDA-01022-E2_Power3
U50 = TPS7A8300RGRR: 2A, Low-Dropout Voltage Regulator for High Speed Communication Systems, RGR0020A (VQFN-20); Alternate PartNumber: TPS7A8300RGRT; Manufacturer: Texas Instruments; SymbolCreator: a0411947; SizeArea_mm2: 12.25; SizeAreaWB_mm2: 20.25; SizeX_mm: 3.5; SizeZ_mm: 1; CompType: IC; U/M: EA

## Sheet TIDA-01022-E2_Power5.SchDoc: Power Supplies
size 431 x 279 mm; Date: Not shown in title block; ApprovedBy: Not shown in title block; CheckedBy: Not shown in title block; Author: Not shown in title block; CompanyName: Not shown in title block; DrawnBy: Avinash N; Engineer: Not shown in title block; Organization: Not shown in title block; Address1: Not shown in title block; Address2: Not shown in title block; Address3: Not shown in title block; Address4: Not shown in title block; DocumentNumber: 1; Revision: Use project parameter SCH_Rev; SheetNumber: 25; SheetTotal: 26; PageSetup: Record=PageOptions¦CenterHorizontal=True¦CenterVertical=True¦PrintScale=1.00¦XCorrection=1.00¦YCorrection=1.00¦PrintKind=0¦BorderSize=5000000¦LeftOffset=0¦BottomOffset=0¦Orientation=2¦PaperLength=1000¦PaperWidth=1000¦Scale=100¦PaperSource=15¦PrintQuality=600¦MediaType=1¦DitherType=10¦PaperKind=Letter¦PrintScaleMode=1
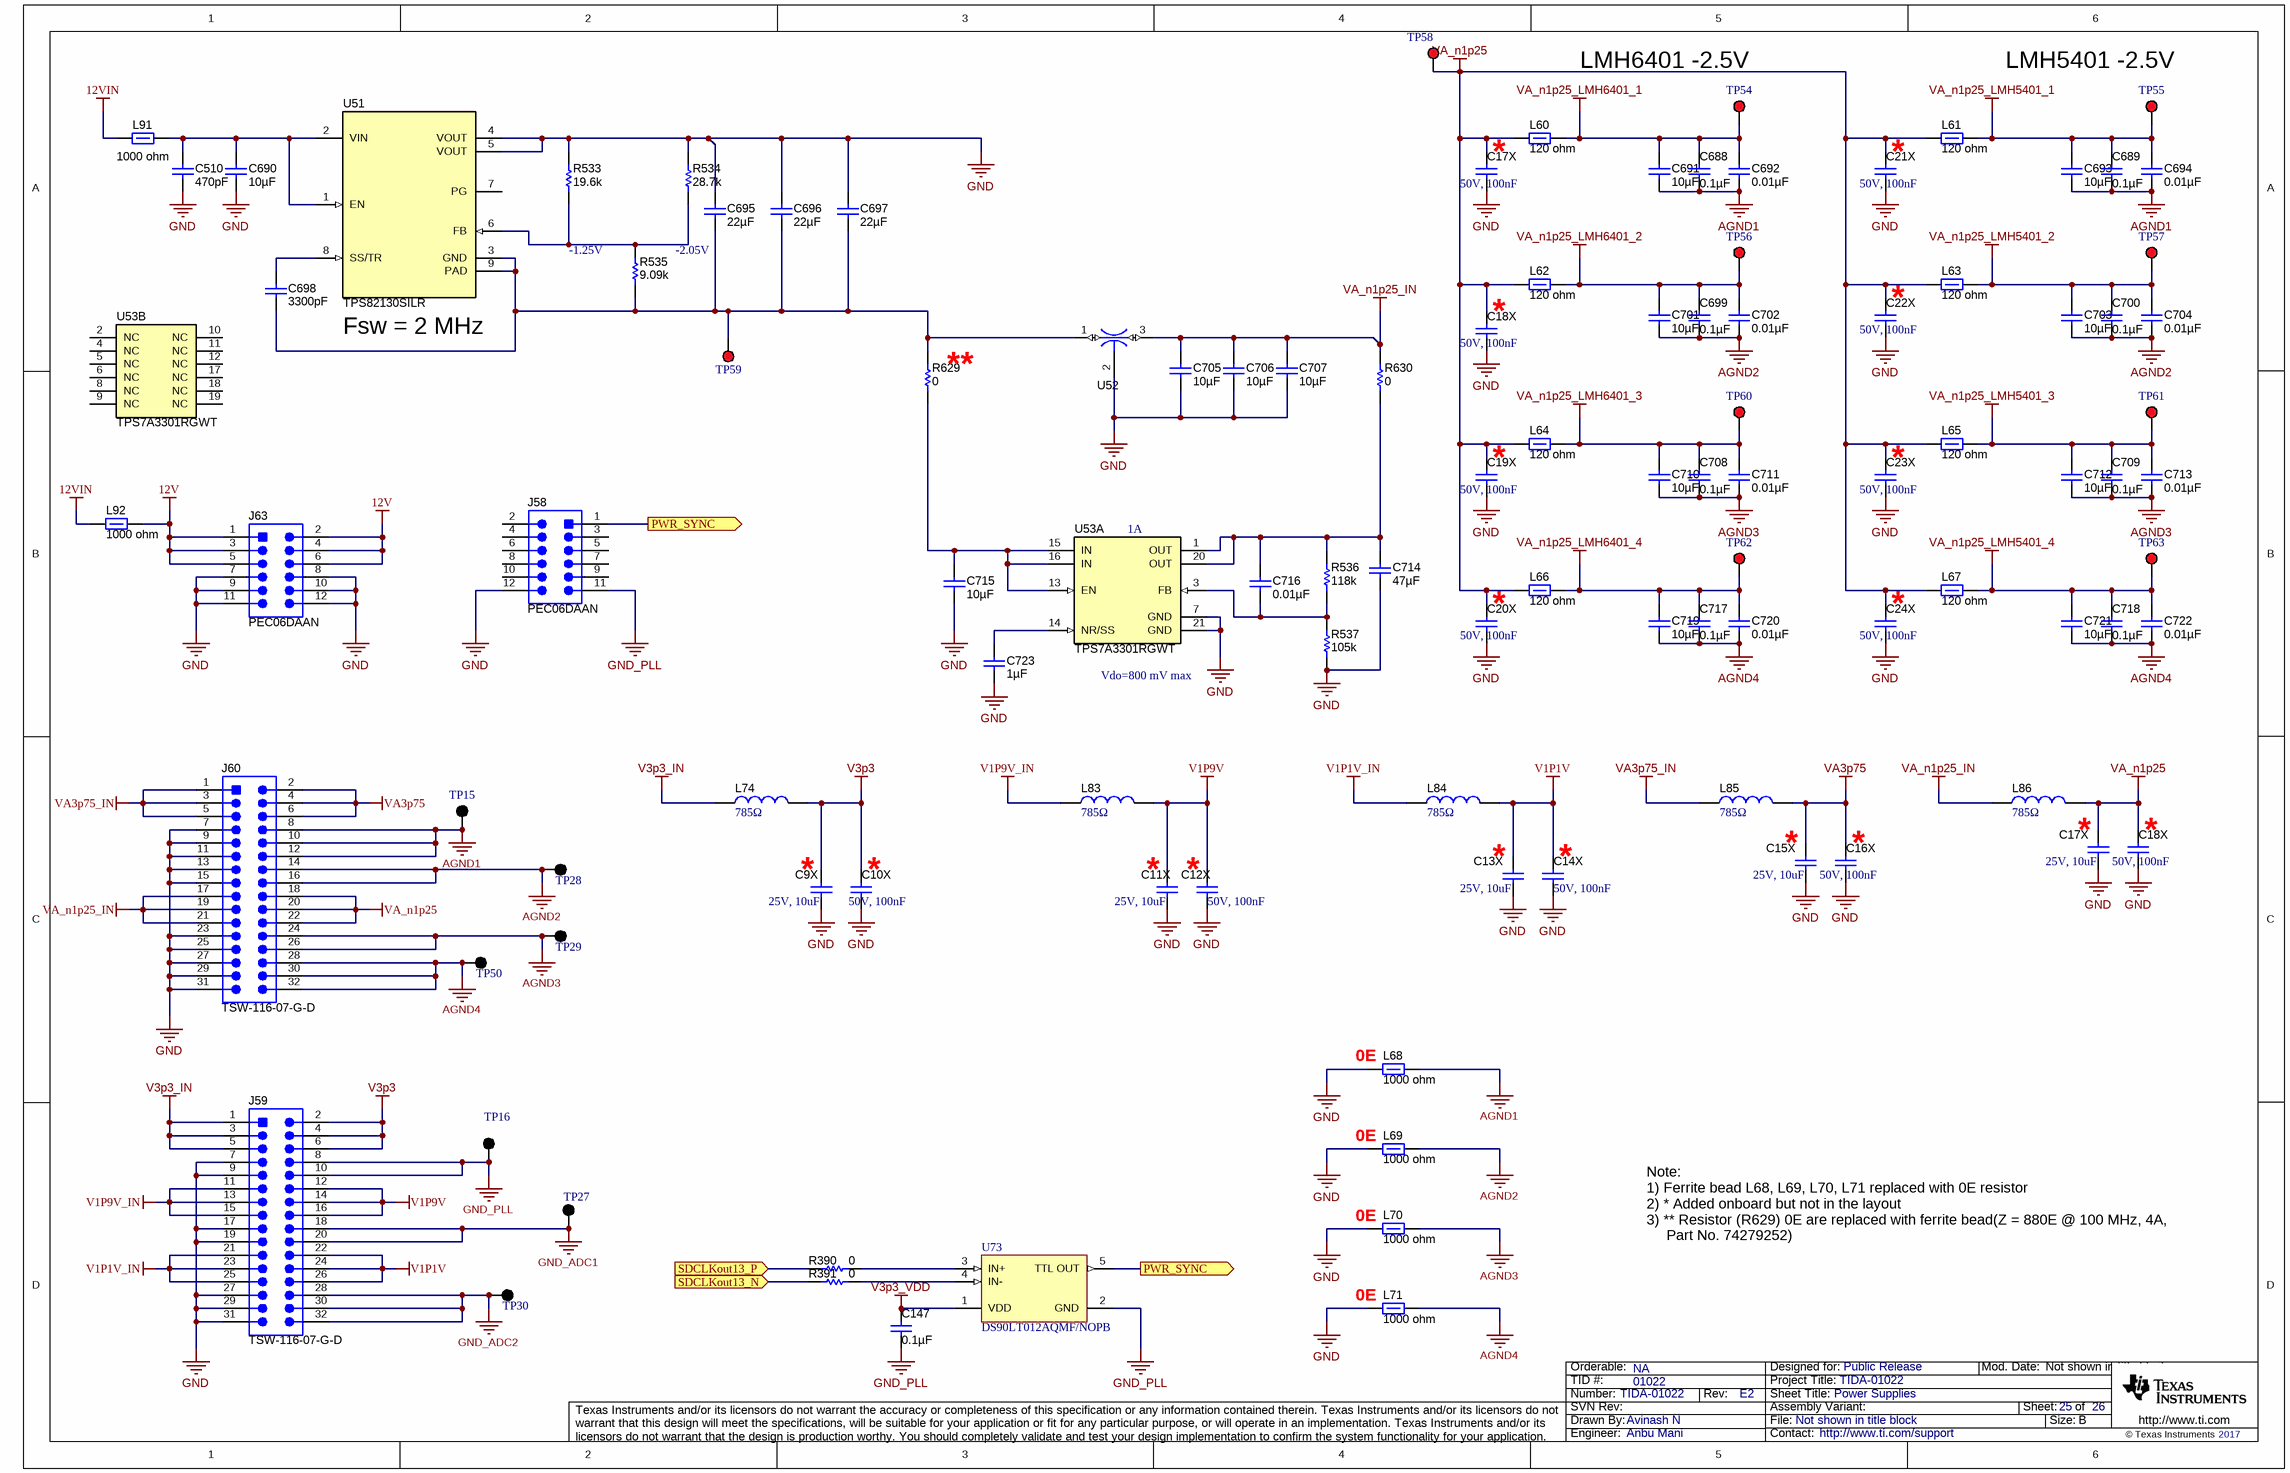
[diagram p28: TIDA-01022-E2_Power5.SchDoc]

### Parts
(Parts that share a designator on the sheet are numbered #1, #2 ... from top to bottom, then left to right.)
C9X  25V, 10uF  [1206_3.2x1.6x1.6mm]
C10X  50V, 100nF  [0603_1.6x0.8x0.8mm_Reflow Soldering]
C11X  25V, 10uF  [1206_3.2x1.6x1.6mm]
C12X  50V, 100nF  [0603_1.6x0.8x0.8mm_Reflow Soldering]
C13X  25V, 10uF  [1206_3.2x1.6x1.6mm]
C14X  50V, 100nF  [0603_1.6x0.8x0.8mm_Reflow Soldering]
C15X  25V, 10uF  [1206_3.2x1.6x1.6mm]
C16X  50V, 100nF  [0603_1.6x0.8x0.8mm_Reflow Soldering]
C17X#1  50V, 100nF  [0603_1.6x0.8x0.8mm_Reflow Soldering]
C17X#2  25V, 10uF  [1206_3.2x1.6x1.6mm]
C18X#1  50V, 100nF  [0603_1.6x0.8x0.8mm_Reflow Soldering]
C18X#2  50V, 100nF  [0603_1.6x0.8x0.8mm_Reflow Soldering]
C19X  50V, 100nF  [0603_1.6x0.8x0.8mm_Reflow Soldering]
C20X  50V, 100nF  [0603_1.6x0.8x0.8mm_Reflow Soldering]
C21X  50V, 100nF  [0603_1.6x0.8x0.8mm_Reflow Soldering]
C22X  50V, 100nF  [0603_1.6x0.8x0.8mm_Reflow Soldering]
C23X  50V, 100nF  [0603_1.6x0.8x0.8mm_Reflow Soldering]
C24X  50V, 100nF  [0603_1.6x0.8x0.8mm_Reflow Soldering]
C147  ValueDisplayed: 0.1µF  [0603]  (hidden comment: CGA3E2X7R1H104K080AA)
C510  ValueDisplayed: 470pF  [0402]  (hidden comment: GRM1555C1H471JA01D)
C688  ValueDisplayed: 0.1µF  [0603]  (hidden comment: CGA3E2X7R1H104K080AA)
C689  ValueDisplayed: 0.1µF  [0603]  (hidden comment: CGA3E2X7R1H104K080AA)
C690  ValueDisplayed: 10µF  [1206_190]  (hidden comment: C3216X7R1E106M160AE)
C691  ValueDisplayed: 10µF  [1206_190]  (hidden comment: C3216X7R1E106M160AE)
C692  ValueDisplayed: 0.01µF  [0603]  (hidden comment: GCM188R71H103KA37D)
C693  ValueDisplayed: 10µF  [1206_190]  (hidden comment: C3216X7R1E106M160AE)
C694  ValueDisplayed: 0.01µF  [0603]  (hidden comment: GCM188R71H103KA37D)
C695  ValueDisplayed: 22µF  [0805_HV]  (hidden comment: JMK212BJ226MG-T)
C696  ValueDisplayed: 22µF  [0805_HV]  (hidden comment: JMK212BJ226MG-T)
C697  ValueDisplayed: 22µF  [0805_HV]  (hidden comment: JMK212BJ226MG-T)
C698  ValueDisplayed: 3300pF  [0603]  (hidden comment: GRM1885C1H332JA01D)
C699  ValueDisplayed: 0.1µF  [0603]  (hidden comment: CGA3E2X7R1H104K080AA)
C700  ValueDisplayed: 0.1µF  [0603]  (hidden comment: CGA3E2X7R1H104K080AA)
C701  ValueDisplayed: 10µF  [1206_190]  (hidden comment: C3216X7R1E106M160AE)
C702  ValueDisplayed: 0.01µF  [0603]  (hidden comment: GCM188R71H103KA37D)
C703  ValueDisplayed: 10µF  [1206_190]  (hidden comment: C3216X7R1E106M160AE)
C704  ValueDisplayed: 0.01µF  [0603]  (hidden comment: GCM188R71H103KA37D)
C705  ValueDisplayed: 10µF  [1206_190]  (hidden comment: C3216X7R1E106M160AE)
C706  ValueDisplayed: 10µF  [1206_190]  (hidden comment: C3216X7R1E106M160AE)
C707  ValueDisplayed: 10µF  [1206_190]  (hidden comment: C3216X7R1E106M160AE)
C708  ValueDisplayed: 0.1µF  [0603]  (hidden comment: CGA3E2X7R1H104K080AA)
C709  ValueDisplayed: 0.1µF  [0603]  (hidden comment: CGA3E2X7R1H104K080AA)
C710  ValueDisplayed: 10µF  [1206_190]  (hidden comment: C3216X7R1E106M160AE)
C711  ValueDisplayed: 0.01µF  [0603]  (hidden comment: GCM188R71H103KA37D)
C712  ValueDisplayed: 10µF  [1206_190]  (hidden comment: C3216X7R1E106M160AE)
C713  ValueDisplayed: 0.01µF  [0603]  (hidden comment: GCM188R71H103KA37D)
C714  ValueDisplayed: 47µF  [0805_HV]  (hidden comment: GRM219R60G476ME44D)
C715  ValueDisplayed: 10µF  [1206_190]  (hidden comment: C3216X7R1E106M160AE)
C716  ValueDisplayed: 0.01µF  [0603]  (hidden comment: GRM188R71H103KA01D)
C717  ValueDisplayed: 0.1µF  [0603]  (hidden comment: CGA3E2X7R1H104K080AA)
C718  ValueDisplayed: 0.1µF  [0603]  (hidden comment: CGA3E2X7R1H104K080AA)
C719  ValueDisplayed: 10µF  [1206_190]  (hidden comment: C3216X7R1E106M160AE)
C720  ValueDisplayed: 0.01µF  [0603]  (hidden comment: GCM188R71H103KA37D)
C721  ValueDisplayed: 10µF  [1206_190]  (hidden comment: C3216X7R1E106M160AE)
C722  ValueDisplayed: 0.01µF  [0603]  (hidden comment: GCM188R71H103KA37D)
C723  ValueDisplayed: 1µF  [0805_HV]  (hidden comment: 08053D105KAT2A)
J58  PEC06DAAN  [CONN_PEC06DAAN]
J59  TSW-116-07-G-D  [TSW-116-07-G-D]
J60  TSW-116-07-G-D  [TSW-116-07-G-D]
J63  PEC06DAAN  [CONN_PEC06DAAN]
L60  ValueDisplayed: 120 ohm  [0603]  (hidden comment: BLM18SG121TN1D)
L61  ValueDisplayed: 120 ohm  [0603]  (hidden comment: BLM18SG121TN1D)
L62  ValueDisplayed: 120 ohm  [0603]  (hidden comment: BLM18SG121TN1D)
L63  ValueDisplayed: 120 ohm  [0603]  (hidden comment: BLM18SG121TN1D)
L64  ValueDisplayed: 120 ohm  [0603]  (hidden comment: BLM18SG121TN1D)
L65  ValueDisplayed: 120 ohm  [0603]  (hidden comment: BLM18SG121TN1D)
L66  ValueDisplayed: 120 ohm  [0603]  (hidden comment: BLM18SG121TN1D)
L67  ValueDisplayed: 120 ohm  [0603]  (hidden comment: BLM18SG121TN1D)
L68  ValueDisplayed: 1000 ohm  [1806_HighSpeed]  (hidden comment: BLM41PG102SN1L)
L69  ValueDisplayed: 1000 ohm  [1806_HighSpeed]  (hidden comment: BLM41PG102SN1L)
L70  ValueDisplayed: 1000 ohm  [1806_HighSpeed]  (hidden comment: BLM41PG102SN1L)
L71  ValueDisplayed: 1000 ohm  [1806_HighSpeed]  (hidden comment: BLM41PG102SN1L)
L74  785Ω  [WE-CBF_1812_High Current]
L83  785Ω  [WE-CBF_1812_High Current]
L84  785Ω  [WE-CBF_1812_High Current]
L85  785Ω  [WE-CBF_1812_High Current]
L86  785Ω  [WE-CBF_1812_High Current]
L91  ValueDisplayed: 1000 ohm  [1806_HighSpeed]  (hidden comment: BLM41PG102SN1L)
L92  ValueDisplayed: 1000 ohm  [1806_HighSpeed]  (hidden comment: BLM41PG102SN1L)
R390  ValueDisplayed: 0  [0402]  (hidden comment: CRCW04020000Z0ED)
R391  ValueDisplayed: 0  [0402]  (hidden comment: CRCW04020000Z0ED)
R533  ValueDisplayed: 19.6k  [0402]  (hidden comment: CRCW040219K6FKED)
R534  ValueDisplayed: 28.7k  [0402]  (hidden comment: CRCW040228K7FKED)
R535  ValueDisplayed: 9.09k  [0402]  (hidden comment: CRCW04029K09FKED)
R536  ValueDisplayed: 118k  [0402]  (hidden comment: CRCW0402118KFKED)
R537  ValueDisplayed: 105k  [0402]  (hidden comment: CRCW0402105KFKED)
R629  ValueDisplayed: 0  [1206]  (hidden comment: CRCW12060000Z0EA)
R630  ValueDisplayed: 0  [1206]  (hidden comment: CRCW12060000Z0EA)
TP15  5001  [Keystone5001]  (value not drawn)
TP16  5001  [Keystone5001]  (value not drawn)
TP27  5001  [Keystone5001]  (value not drawn)
TP28  5001  [Keystone5001]  (value not drawn)
TP29  5001  [Keystone5001]  (value not drawn)
TP30  5001  [Keystone5001]  (value not drawn)
TP50  5001  [Keystone5001]  (value not drawn)
TP54  5000  [Keystone5000]  (value not drawn)
TP55  5000  [Keystone5000]  (value not drawn)
TP56  5000  [Keystone5000]  (value not drawn)
TP57  5000  [Keystone5000]  (value not drawn)
TP58  5000  [Keystone5000]  (value not drawn)
TP59  5000  [Keystone5000]  (value not drawn)
TP60  5000  [Keystone5000]  (value not drawn)
TP61  5000  [Keystone5000]  (value not drawn)
TP62  5000  [Keystone5000]  (value not drawn)
TP63  5000  [Keystone5000]  (value not drawn)
U51  TPS82130SILR  [SIL0008D_SMD]
U52  NFM31PC276B0J3L  [Murata_NFM31P]  (value not drawn)
U53  TPS7A3301RGWT  [RGW0020A]  (parts A,B of 2)
U73  DS90LT012AQMF/NOPB  [MF05A_N]

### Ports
PWR_SYNC (out), SDCLKout13_N (in), SDCLKout13_P (in)

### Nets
12V: J63.1 J63.2 J63.3 J63.4 J63.5 J63.6 L92.1
12VIN: L91.1 L92.2
AGND1: C688.2 C689.2 C691.1 C692.2 C693.1 C694.2 C699.2 C700.2 C701.1 C702.2 C703.1 C704.2 C708.2 C709.2 C710.1 C711.2 C712.1 C713.2 C717.2 C718.2 C719.1 C720.2 C721.1 C722.2 J60.8 J60.10 J60.12 J60.14 J60.16 J60.24 J60.26 J60.28 J60.30 J60.32 L68.2 L69.2 L70.2 L71.2 TP15.1 TP28.1 TP29.1 TP50.1  [also labelled AGND2, AGND3, AGND4]  [project net AGND]
GND: C9X.1 C10X.1 C11X.1 C12X.1 C13X.1 C14X.1 C15X.1 C16X.1 C17X#1.1 C17X#2.1 C18X#1.1 C18X#2.1 C19X.1 C20X.1 C21X.1 C22X.1 C23X.1 C24X.1 C510.2 C690.2 C695.1 C696.1 C697.1 C705.1 C706.1 C707.1 C714.2 C715.1 C723.2 J58.12 J59.7 J59.9 J59.17 J59.19 J59.27 J59.29 J59.31 J60.7 J60.9 J60.11 J60.13 J60.15 J60.23 J60.25 J60.27 J60.29 J60.31 J63.7 J63.8 J63.9 J63.10 J63.11 J63.12 L68.1 L69.1 L70.1 L71.1 R533.2 R534.2 R537.1 U51.4(VOUT) U51.5(VOUT) U52.2 U53.7(GND) U53.21(GND)
GND_ADC1: C147.2 J58.11 J59.8 J59.10 J59.18 J59.20 J59.28 J59.30 J59.32 TP16.1 TP27.1 TP30.1 U73.2(GND)  [also labelled GND_ADC2, GND_PLL]  [project net DGND]
V1P1V: C13X.2 C14X.2 J59.22 J59.24 J59.26 L84.2
V1P1V_IN: J59.21 J59.23 J59.25 L84.1
V1P9V: C11X.2 C12X.2 J59.12 J59.14 J59.16 L83.2
V1P9V_IN: J59.11 J59.13 J59.15 L83.1
V3p3: C9X.2 C10X.2 J59.2 J59.4 J59.6 L74.2
V3p3_IN: J59.1 J59.3 J59.5 L74.1
V3p3_VDD: C147.1 U73.1(VDD)
VA3p75: C15X.2 C16X.2 J60.2 J60.4 J60.6 L85.2
VA3p75_IN: J60.1 J60.3 J60.5 L85.1
VA_n1p25: C17X#1.2 C17X#2.2 C18X#1.2 C18X#2.2 C19X.2 C20X.2 C21X.2 C22X.2 C23X.2 C24X.2 J60.18 J60.20 J60.22 L60.1 L61.1 L62.1 L63.1 L64.1 L65.1 L66.1 L67.1 L86.2 TP58.1
VA_n1p25_IN: C705.2 C706.2 C707.2 J60.17 J60.19 J60.21 L86.1 R630.2 U52.3
VA_n1p25_LMH5401_1: C689.1 C693.2 C694.1 L61.2 TP55.1
VA_n1p25_LMH5401_2: C700.1 C703.2 C704.1 L63.2 TP57.1
VA_n1p25_LMH5401_3: C709.1 C712.2 C713.1 L65.2 TP61.1
VA_n1p25_LMH5401_4: C718.1 C721.2 C722.1 L67.2 TP63.1
VA_n1p25_LMH6401_1: C688.1 C691.2 C692.1 L60.2 TP54.1
VA_n1p25_LMH6401_2: C699.1 C701.2 C702.1 L62.2 TP56.1
VA_n1p25_LMH6401_3: C708.1 C710.2 C711.1 L64.2 TP60.1
VA_n1p25_LMH6401_4: C717.1 C719.2 C720.1 L66.2 TP62.1
PWR_SYNC: J58.1 U73.5(TTL_OUT) ; port PWR_SYNC
SDCLKout13_N: R391.1 ; port SDCLKout13_N
SDCLKout13_P: R390.1 ; port SDCLKout13_P
NetC510_1: C510.1 C690.1 L91.2 U51.1(EN) U51.2(VIN)
NetC695_2: C695.2 C696.2 C697.2 C698.1 R535.1 R629.2 TP59.1 U51.3(GND) U51.9(PAD) U52.1
NetC698_2: C698.2 U51.8(SS/TR)
NetC714_1: C714.1 C716.1 R536.2 R630.1 U53.1(OUT) U53.20(OUT)
NetC715_2: C715.2 R629.1 U53.13(EN) U53.15(IN) U53.16(IN)
NetC716_2: C716.2 R536.1 R537.2 U53.3(FB)
NetC723_1: C723.1 U53.14(NR/SS)
NetR390_2: R390.2 U73.3(IN+)
NetR391_2: R391.2 U73.4(IN-)
NetR533_1: R533.1 R534.1 R535.2 U51.6(FB)

Not connected (* = marked no-connect by the designer): J58 2 3 4 5 6 7 8 9 10; U51 7(PG); U53 2(NC) 4(NC) 5(NC) 6(NC) 8(NC) 9(NC) 10(NC) 11(NC) 12(NC) 17(NC) 18(NC) 19(NC)

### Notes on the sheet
- (near TP54) LMH6401 -2.5V
- (near TP55) LMH5401 -2.5V
- (near C17X#1) *
- (near C21X) *
- (near R535) -1.25V
- -2.05V
- (near C22X) *
- (near U51) Fsw = 2 MHz
- (near R629) *
- (near C18X#1) *
- (near C19X) *
- (near C23X) *
- (near U53) 1A
- (near C20X) *
- (near C24X) *
- (near U53) Vdo=800 mV max
- (near C17X#2) *
- (near C18X#2) *
- (near C9X) *
- (near C10X) *
- (near C11X) *
- (near C12X) *
- (near C13X) *
- (near C14X) *
- (near C15X) *
- (near C16X) *
- (near L68) 0E
- (near L69) 0E
- (near L70) 0E
- (near L71) 0E
- Note:
  1) Ferrite bead L68, L69, L70, L71 replaced with 0E resistor
  2) * Added onboard but not in the layout
  3) ** Resistor (R629) 0E are replaced with ferrite bead(Z = 880E @ 100 MHz, 4A,
  Part No. 74279252)

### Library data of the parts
C9X C11X C13X C15X C17X#2 = 885012208069: WCAP-CSGP Ceramic Capacitors, 1206, X7R, 25V, 10uF; Rated Voltage: 25V DC
C10X C12X C14X C16X C17X#1 C18X#1 C18X#2 C19X C20X C21X C22X C23X C24X = 885012206095: as C25X on sheet TIDA-01022-E2_Power3
C147 C688 C689 C699 C700 C708 C709 C717 C718 = CGA3E2X7R1H104K080AA: as C485 on sheet TIDA-01022-E2_Power3
C510 = GRM1555C1H471JA01D: as C371 on sheet TIDA-01022-E2_Power3
C690 C691 C693 C701 C703 C705-C707 C710 C712 C715 C719 C721 = C3216X7R1E106M160AE: as C487 on sheet TIDA-01022-E2_Power3
C692 C694 C702 C704 C711 C713 C720 C722 = GCM188R71H103KA37D: as C488 on sheet TIDA-01022-E2_Power3
C695-C697 = JMK212BJ226MG-T: as C601 on sheet TIDA-01022-E2_Power3
C698 = GRM1885C1H332JA01D: as C608 on sheet TIDA-01022-E2_Power3
C714 = GRM219R60G476ME44D: as C615 on sheet TIDA-01022-E2_Power3
C716 = GRM188R71H103KA01D: as C619 on sheet TIDA-01022-E2_Power3
C723 = 08053D105KAT2A: CAP, CERM, 1 µF, 25 V, +/- 10%, X5R, 0805; Manufacturer: AVX; Polarized: N; CompType: Capacitor; Value: 1uF; U/M: EA; Cap_F: 0.000001; Tolerance_%: 10; ESR_ohm: 0.012; Value1: 0.012 ohm; VDC_V: 25; Value2: 25V; TaMin_C: -55; TaMax_C: 85; Cap_Case: 0805; SizeArea_mm2: 2.5; SizeAreaWB_mm2: 6.75; SizeX_mm: 2; SizeY_mm: 1.25; SizeZ_mm: 1.45; AEC Category: Q200
J58 J63 = PEC06DAAN: Header, 100mil, 6x2, Tin, TH; Manufacturer: Sullins Connector Solutions; SymbolCreator: a0412235; Pitch_mm: 2.54; Gender: Male; Shrouded: N; Row_Count: 2; Current_A: 3; Voltage_V: 1800; Cert_UL: Y; Green_Lifecycle: Not Set; Green_REACh: Incomplete
J59 J60 = TSW-116-07-G-D: Header, 100mil, 16x2, Gold, TH; Manufacturer: Samtec; SymbolCreator: a0412235; Pitch_mm: 2.54; Gender: Male; Shrouded: N; Row_Count: 2; Current_A: 6.3; Voltage_V: 550; Cert_CSA: Y; Green_Lifecycle: Active; Green_REACh: Passed
L60-L67 = BLM18SG121TN1D: as L48-L55 on sheet TIDA-01022-E2_Power4
L68-L71 L91 L92 = BLM41PG102SN1L: as L41-L47 on sheet TIDA-01022-E2_Power3
L74 L83-L86 = WE-CBF, 742792515: WE-CBF SMD EMI Suppression Ferrite Bead, 1812, 785Ω; Type: High Current
R390 R391 = CRCW04020000Z0ED: as R519-R524 on sheet TIDA-01022-E2_Power3
R533 = CRCW040219K6FKED: RES, 19.6 k, 1%, 0.063 W, 0402; Manufacturer: Vishay-Dale; CompType: Resistor; Value: 19.6k; Res_ohm: 19600; Value_Code: 19k6; Tolerance_%: 1; Power_W: 0.063; Value2: 0.063W; VDC_V: 50; TempCo: 100 ppm/C; SizeArea_mm2: 0.5; SizeZ_mm: 0.6; EIA_Code: E96; U/M: EA; AEC Category: Q200
R534 = CRCW040228K7FKED: RES, 28.7 k, 1%, 0.063 W, 0402; Manufacturer: Vishay-Dale; CompType: Resistor; Value: 28.7k; Res_ohm: 28700; Value_Code: 28k7; Tolerance_%: 1; Power_W: 0.063; Value2: 0.063W; VDC_V: 50; TempCo: 100 ppm/C; SizeArea_mm2: 0.5; SizeZ_mm: 0.6; EIA_Code: E96; U/M: EA; AEC Category: Q200
R535 = CRCW04029K09FKED: RES, 9.09 k, 1%, 0.063 W, 0402; Manufacturer: Vishay-Dale; CompType: Resistor; Value: 9.09k; Res_ohm: 9090; Value_Code: 9k09; Tolerance_%: 1; Power_W: 0.063; Value2: 0.063W; VDC_V: 50; TempCo: 100 ppm/C; SizeArea_mm2: 0.5; SizeZ_mm: 0.6; EIA_Code: E96; U/M: EA; AEC Category: Q200
R536 = CRCW0402118KFKED: RES, 118 k, 1%, 0.063 W, 0402; Manufacturer: Vishay-Dale; CompType: Resistor; Value: 118k; Res_ohm: 118000; Tolerance_%: 1; Power_W: 0.063; Value2: 0.063W; VDC_V: 50; TempCo: 100 ppm/C; SizeArea_mm2: 0.5; SizeZ_mm: 0.6; EIA_Code: E96; U/M: EA; AEC Category: Q200
R537 = CRCW0402105KFKED: RES, 105 k, 1%, 0.063 W, 0402; Manufacturer: Vishay-Dale; CompType: Resistor; Value: 105k; Res_ohm: 105000; Tolerance_%: 1; Power_W: 0.063; Value2: 0.063W; VDC_V: 50; TempCo: 100 ppm/C; SizeArea_mm2: 0.5; SizeZ_mm: 0.6; EIA_Code: E96; U/M: EA; AEC Category: Q200
R629 R630 = CRCW12060000Z0EA: as R621 on sheet TIDA-01022-E2_Power3
TP15 TP16 TP27-TP30 TP50 = 5001: Test Point, Miniature, Black, TH; Manufacturer: Keystone; CompType: Test Point Loop; ContactFinish: Silver; Green_Lifecycle: Active; Green_REACh: Passed
TP54-TP63 = 5000: as TP24 on sheet TIDA-01022-E2_Power3
U51 = TPS82130SILR: as U45 on sheet TIDA-01022-E2_Power3
U52 = NFM31PC276B0J3L: as U46 on sheet TIDA-01022-E2_Power3
U53 = TPS7A3301RGWT: Single Output High PSRR LDO, 1 A, Adjustable -1.18 to -33 V Output, -3 to -36 V Input, with Ultra-Low Noise, 20-pin VQFN (RGW), -40 to 125 degC, Green (RoHS & no Sb/Br); Manufacturer: Texas Instruments; Alternate PartNumber: Equivalent; Accuracy(%): 1.5; Iout(Max)(A): 1; Iq(Typ)(mA): 0.21; SubFamily: Single Channel LDO; Vdo(Typ)(mV): 290
U73 = DS90LT012AQMF/NOPB: Automotive LVDS Differential Line Receiver, 5-pin SOT-23, Pb-Free; Manufacturer: Texas Instruments; PackageTopMarking: N03Q*XTT; PowerWise: N; CompType: Interface IC

## Sheet TIDA-01022-E2_Hardware.SchDoc: Hardware
size 431 x 279 mm; Date: Not shown in title block; ApprovedBy: Not shown in title block; CheckedBy: Not shown in title block; Author: Not shown in title block; CompanyName: Not shown in title block; DrawnBy: Avinash N; Engineer: Not shown in title block; Organization: Not shown in title block; Address1: Not shown in title block; Address2: Not shown in title block; Address3: Not shown in title block; Address4: Not shown in title block; DocumentNumber: 1; Revision: Use project parameter SCH_Rev; SheetNumber: 26; SheetTotal: 26; PageSetup: Record=PageOptions¦CenterHorizontal=True¦CenterVertical=True¦PrintScale=1.00¦XCorrection=1.00¦YCorrection=1.00¦PrintKind=0¦BorderSize=5000000¦LeftOffset=0¦BottomOffset=0¦Orientation=2¦PaperLength=1000¦PaperWidth=1000¦Scale=100¦PaperSource=15¦PrintQuality=600¦MediaType=1¦DitherType=10¦PaperKind=Letter¦PrintScaleMode=1
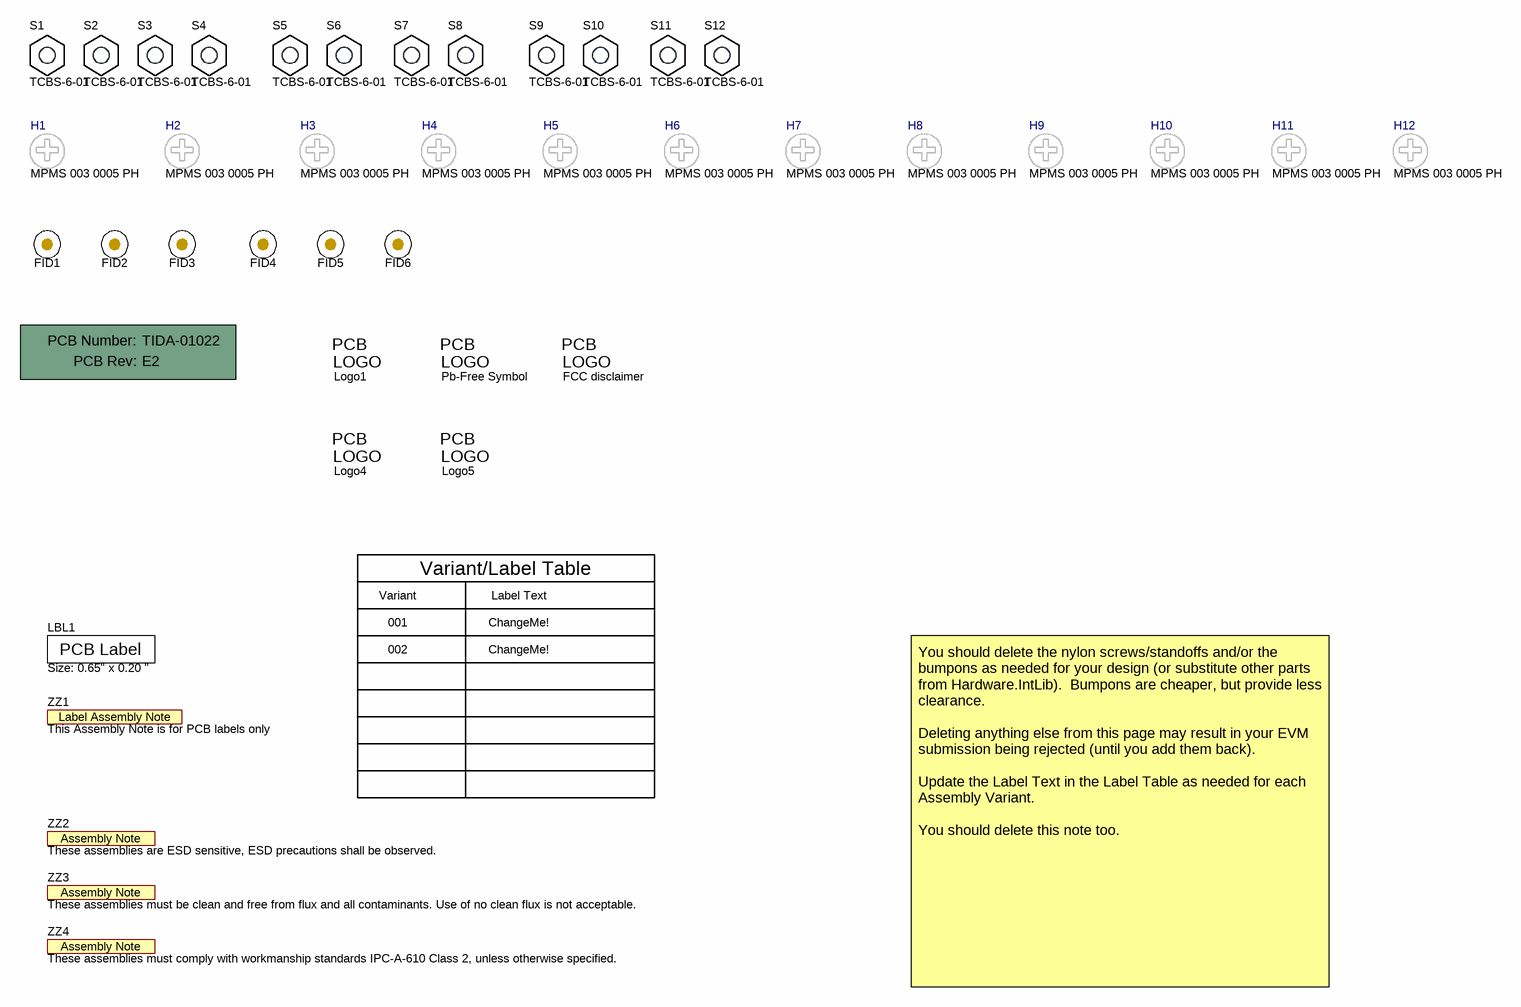
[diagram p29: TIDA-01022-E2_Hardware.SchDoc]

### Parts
!PCB1  Printed Circuit Board  (value not drawn)  (mechanical)
FID1  Fiducial  [Fiducial10-20]  (value not drawn)
FID2  Fiducial  [Fiducial10-20]  (value not drawn)
FID3  Fiducial  [Fiducial10-20]  (value not drawn)
FID4  Fiducial  [Fiducial10-20]  (value not drawn)
FID5  Fiducial  [Fiducial10-20]  (value not drawn)
FID6  Fiducial  [Fiducial10-20]  (value not drawn)
H1  MPMS 003 0005 PH  [BuildingFastener_MPMS_003_0005_PH]  (mechanical)
H2  MPMS 003 0005 PH  [BuildingFastener_MPMS_003_0005_PH]  (mechanical)
H3  MPMS 003 0005 PH  [BuildingFastener_MPMS_003_0005_PH]  (mechanical)
H4  MPMS 003 0005 PH  [BuildingFastener_MPMS_003_0005_PH]  (mechanical)
H5  MPMS 003 0005 PH  [BuildingFastener_MPMS_003_0005_PH]  (mechanical)
H6  MPMS 003 0005 PH  [BuildingFastener_MPMS_003_0005_PH]  (mechanical)
H7  MPMS 003 0005 PH  [BuildingFastener_MPMS_003_0005_PH]  (mechanical)
H8  MPMS 003 0005 PH  [BuildingFastener_MPMS_003_0005_PH]  (mechanical)
H9  MPMS 003 0005 PH  [BuildingFastener_MPMS_003_0005_PH]  (mechanical)
H10  MPMS 003 0005 PH  [BuildingFastener_MPMS_003_0005_PH]  (mechanical)
H11  MPMS 003 0005 PH  [BuildingFastener_MPMS_003_0005_PH]  (mechanical)
H12  MPMS 003 0005 PH  [BuildingFastener_MPMS_003_0005_PH]  (mechanical)
LBL1  Size: 0.65" x 0.20 "  [Label_650x200]
Logo1  ESD Susceptible  [ESD_Overlay_Large]  (value not drawn)  (no BOM)
Logo2  Pb-Free Symbol  [Pb-Free_Overlay_Small]  (no BOM)
Logo3  FCC disclaimer  [FCC_disclaimer]  (no BOM)
Logo4  EU RoHS Exempt Logo  [EURoHS_Exempt_60mil]  (value not drawn)  (no BOM)
Logo5  CAUTION.  READ USER GUIDE BEFORE USE  [IEC_Caution_Medium]  (value not drawn)  (no BOM)
S1  TCBS-6-01  [TCBS-6-01]
S2  TCBS-6-01  [TCBS-6-01]
S3  TCBS-6-01  [TCBS-6-01]
S4  TCBS-6-01  [TCBS-6-01]
S5  TCBS-6-01  [TCBS-6-01]
S6  TCBS-6-01  [TCBS-6-01]
S7  TCBS-6-01  [TCBS-6-01]
S8  TCBS-6-01  [TCBS-6-01]
S9  TCBS-6-01  [TCBS-6-01]
S10  TCBS-6-01  [TCBS-6-01]
S11  TCBS-6-01  [TCBS-6-01]
S12  TCBS-6-01  [TCBS-6-01]
ZZ1  This Assembly Note is for PCB labels only  [AssemblyNoteLabel]  (no BOM)
ZZ2  These assemblies are ESD sensitive, ESD precautions shall be observed.  [AssemblyNote]  (no BOM)
ZZ3  These assemblies must be clean and free from flux and all contaminants. Use of no clean flux is not acceptable.  [AssemblyNote]  (no BOM)
ZZ4  These assemblies must comply with workmanship standards IPC-A-610 Class 2, unless otherwise specified.  [AssemblyNote]  (no BOM)

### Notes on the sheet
- Variant
- Variant/Label Table
- Label Text
- 001
- 002
- ChangeMe!
- You should delete the nylon screws/standoffs and/or the bumpons as needed for your design (or substitute other parts from Hardware.IntLib).  Bumpons are cheaper, but provide less clearance.
  Deleting anything else from this page may result in your EVM submission being rejected (until you add them back).
  Update the Label Text in the Label Table as needed for each Assembly Variant.
  You should delete this note too.

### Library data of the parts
!PCB1 = PCB: Manufacturer: Any; PartNumber: TIDA-01022; SymbolCreator: a0412235
FID1-FID6 = Fiducial: Fiducial mark.  There is nothing to buy or mount.; SymbolCreator: codlsc
H1-H12 = MPMS 003 0005 PH: MACHINE SCREW PAN PHILLIPS M3 5mm; Manufacturer: B&F Fastener Supply; CompType: Hardware
LBL1 = THT-14-423-10: Thermal Transfer Printable Labels, 0.650" W x 0.200" H - 10,000 per roll; Manufacturer: Brady; SymbolCreator: a0412235; CompType: Label
Logo1 = ESD_Susceptible: ESD Susceptible Symbol; SymbolCreator: a0412235
Logo2 = Pb-Free: SymbolCreator: a0412235
Logo3 = FCC_disclaimer: SymbolCreator: codlsc
Logo4 = EURoHS_Exempt: SymbolCreator: a0412235
Logo5 = IEC_Caution: IEC 61010-1 Caution Warning; SymbolCreator: a0412235
S1-S12 = TCBS-6-01: HEX STANDOFF SPACER, 9.53 mm; Manufacturer: Richco Plastics; SymbolCreator: a0412235
ZZ1 = AssemblyNoteLabel: SymbolCreator: a0412235
ZZ2-ZZ4 = AssemblyNote: SymbolCreator: codlsc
